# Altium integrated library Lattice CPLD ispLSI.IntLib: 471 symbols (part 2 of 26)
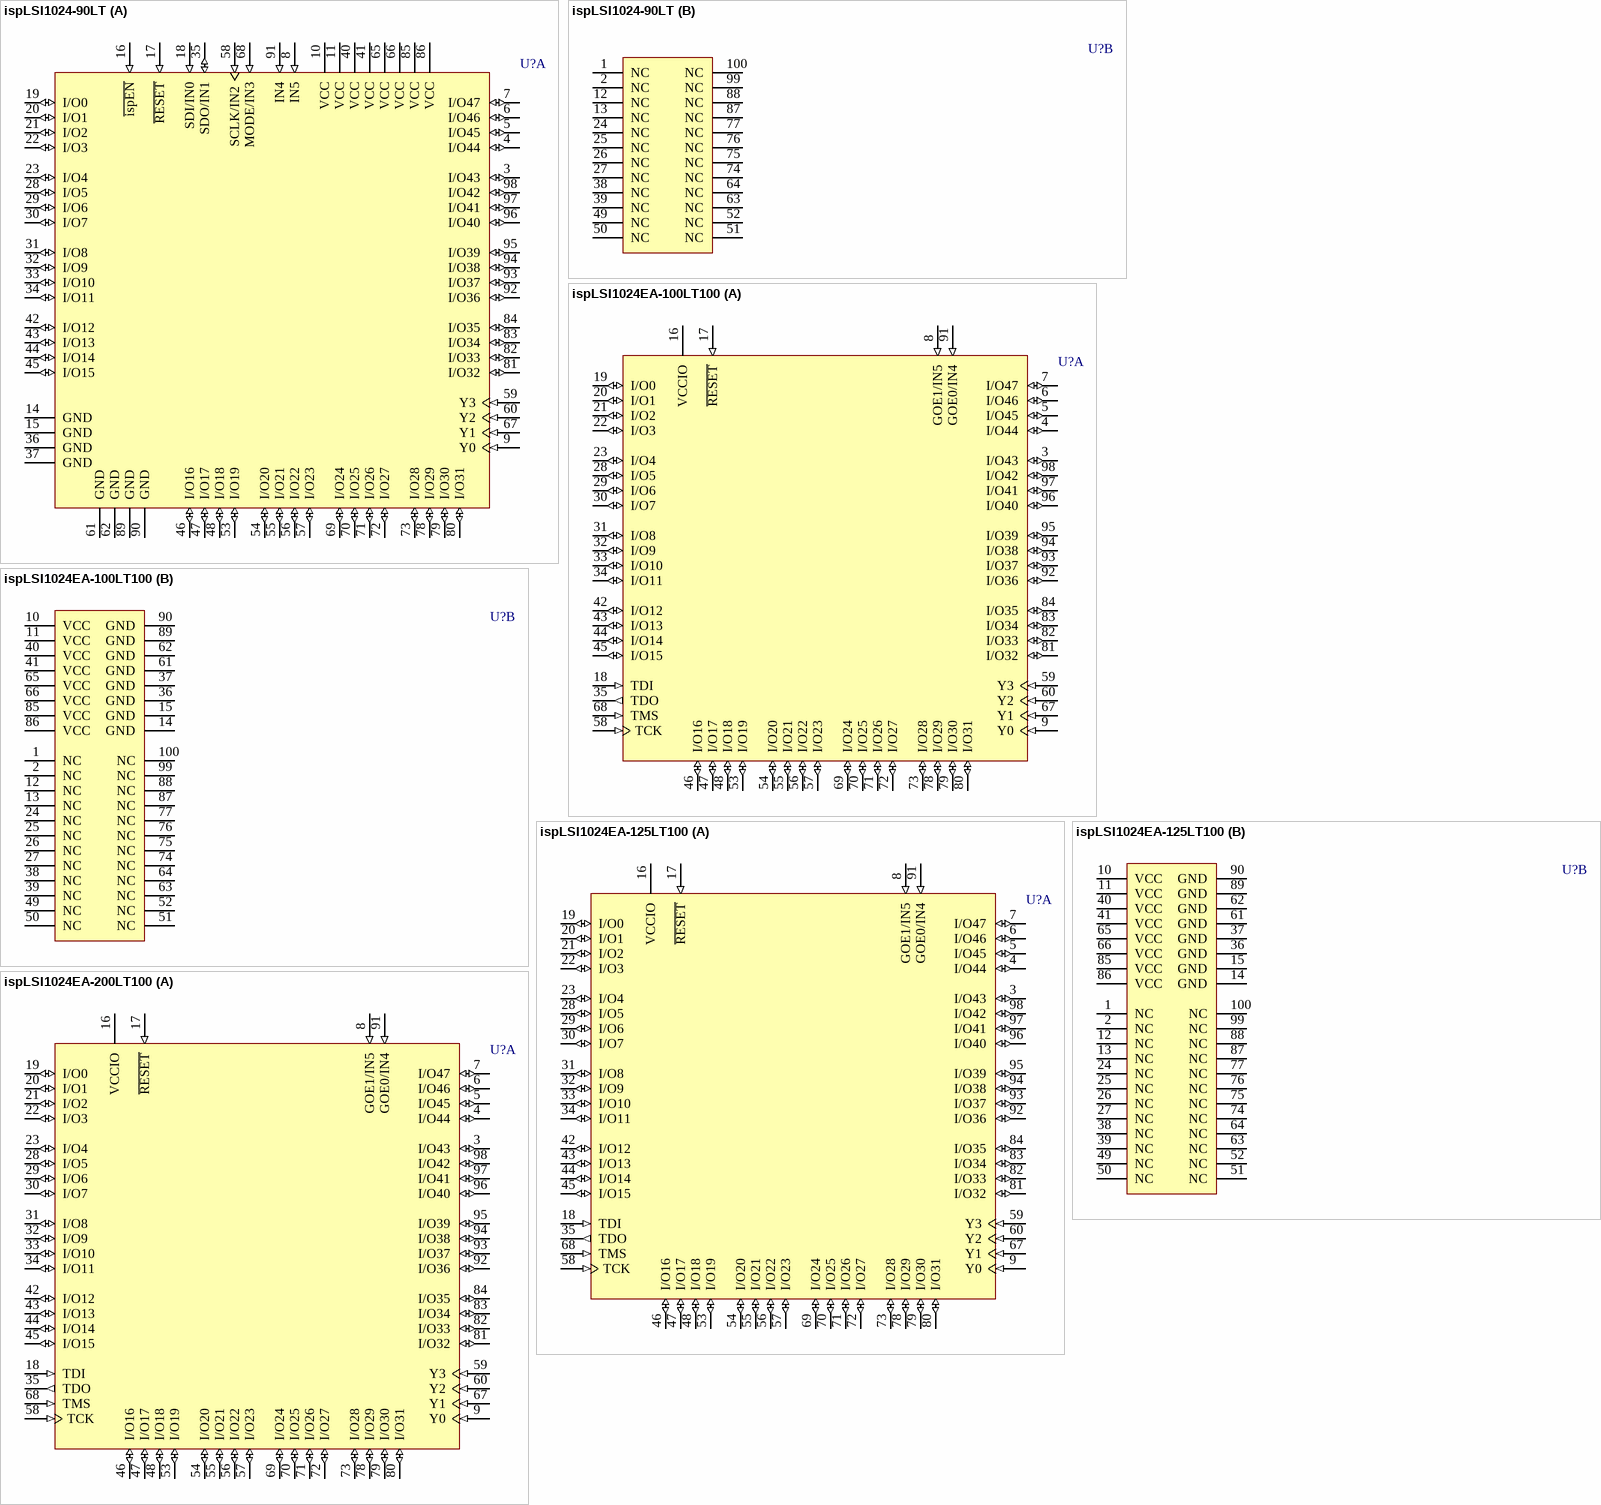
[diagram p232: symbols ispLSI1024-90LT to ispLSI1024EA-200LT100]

## ispLSI1024EA-100LT100
designator U?
In-System Programmable High-Density PLD; Note: Pins 8 and 91 have dual function capability which is software selectable.
footprint TQFP100_N (Thin QFP, 100-Leads, Body 14x14mm, Pitch 0.5mm, IPC Medium Density)
footprint TQFP100_L (Thin QFP, 100-Leads, Body 14x14mm, Pitch 0.5mm, IPC High Density)
footprint TQFP100_M (Thin QFP, 100-Leads, Body 14x14mm, Pitch 0.5mm, IPC Low Density)
3D model 1024EA-TQFP100 (100-Pin Thin Quad Flat Pack (TQFP100))
part A pins: 3 I/O43 (io), 4 I/O44 (io), 5 I/O45 (io), 6 I/O46 (io), 7 I/O47 (io), 8 GOE1/IN5 (in), 9 Y0 (in), 16 VCCIO (power), 17 ~{RESET} (in), 18 TDI (in), 19 I/O0 (io), 20 I/O1 (io), 21 I/O2 (io), 22 I/O3 (io), 23 I/O4 (io), 28 I/O5 (io), 29 I/O6 (io), 30 I/O7 (io), 31 I/O8 (io), 32 I/O9 (io), 33 I/O10 (io), 34 I/O11 (io), 35 TDO (out), 42 I/O12 (io), 43 I/O13 (io), 44 I/O14 (io), 45 I/O15 (io), 46 I/O16 (io), 47 I/O17 (io), 48 I/O18 (io), 53 I/O19 (io), 54 I/O20 (io), 55 I/O21 (io), 56 I/O22 (io), 57 I/O23 (io), 58 TCK (in), 59 Y3 (in), 60 Y2 (in), 67 Y1 (in), 68 TMS (in), 69 I/O24 (io), 70 I/O25 (io), 71 I/O26 (io), 72 I/O27 (io), 73 I/O28 (io), 78 I/O29 (io), 79 I/O30 (io), 80 I/O31 (io), 81 I/O32 (io), 82 I/O33 (io), 83 I/O34 (io), 84 I/O35 (io), 91 GOE0/IN4 (in), 92 I/O36 (io), 93 I/O37 (io), 94 I/O38 (io), 95 I/O39 (io), 96 I/O40 (io), 97 I/O41 (io), 98 I/O42 (io)
part B pins: 1 NC, 2 NC, 10 VCC (power), 11 VCC (power), 12 NC, 13 NC, 14 GND (power), 15 GND (power), 24 NC, 25 NC, 26 NC, 27 NC, 36 GND (power), 37 GND (power), 38 NC, 39 NC, 40 VCC (power), 41 VCC (power), 49 NC, 50 NC, 51 NC, 52 NC, 61 GND (power), 62 GND (power), 63 NC, 64 NC, 65 VCC (power), 66 VCC (power), 74 NC, 75 NC, 76 NC, 77 NC, 85 VCC (power), 86 VCC (power), 87 NC, 88 NC, 89 GND (power), 90 GND (power), 99 NC, 100 NC

## ispLSI1024EA-125LT100
designator U?
In-System Programmable High-Density PLD; Note: Pins 8 and 91 have dual function capability which is software selectable.
footprint TQFP100_N (Thin QFP, 100-Leads, Body 14x14mm, Pitch 0.5mm, IPC Medium Density)
footprint TQFP100_L (Thin QFP, 100-Leads, Body 14x14mm, Pitch 0.5mm, IPC High Density)
footprint TQFP100_M (Thin QFP, 100-Leads, Body 14x14mm, Pitch 0.5mm, IPC Low Density)
3D model 1024EA-TQFP100 (100-Pin Thin Quad Flat Pack (TQFP100))
part A pins: 3 I/O43 (io), 4 I/O44 (io), 5 I/O45 (io), 6 I/O46 (io), 7 I/O47 (io), 8 GOE1/IN5 (in), 9 Y0 (in), 16 VCCIO (power), 17 ~{RESET} (in), 18 TDI (in), 19 I/O0 (io), 20 I/O1 (io), 21 I/O2 (io), 22 I/O3 (io), 23 I/O4 (io), 28 I/O5 (io), 29 I/O6 (io), 30 I/O7 (io), 31 I/O8 (io), 32 I/O9 (io), 33 I/O10 (io), 34 I/O11 (io), 35 TDO (out), 42 I/O12 (io), 43 I/O13 (io), 44 I/O14 (io), 45 I/O15 (io), 46 I/O16 (io), 47 I/O17 (io), 48 I/O18 (io), 53 I/O19 (io), 54 I/O20 (io), 55 I/O21 (io), 56 I/O22 (io), 57 I/O23 (io), 58 TCK (in), 59 Y3 (in), 60 Y2 (in), 67 Y1 (in), 68 TMS (in), 69 I/O24 (io), 70 I/O25 (io), 71 I/O26 (io), 72 I/O27 (io), 73 I/O28 (io), 78 I/O29 (io), 79 I/O30 (io), 80 I/O31 (io), 81 I/O32 (io), 82 I/O33 (io), 83 I/O34 (io), 84 I/O35 (io), 91 GOE0/IN4 (in), 92 I/O36 (io), 93 I/O37 (io), 94 I/O38 (io), 95 I/O39 (io), 96 I/O40 (io), 97 I/O41 (io), 98 I/O42 (io)
part B pins: 1 NC, 2 NC, 10 VCC (power), 11 VCC (power), 12 NC, 13 NC, 14 GND (power), 15 GND (power), 24 NC, 25 NC, 26 NC, 27 NC, 36 GND (power), 37 GND (power), 38 NC, 39 NC, 40 VCC (power), 41 VCC (power), 49 NC, 50 NC, 51 NC, 52 NC, 61 GND (power), 62 GND (power), 63 NC, 64 NC, 65 VCC (power), 66 VCC (power), 74 NC, 75 NC, 76 NC, 77 NC, 85 VCC (power), 86 VCC (power), 87 NC, 88 NC, 89 GND (power), 90 GND (power), 99 NC, 100 NC

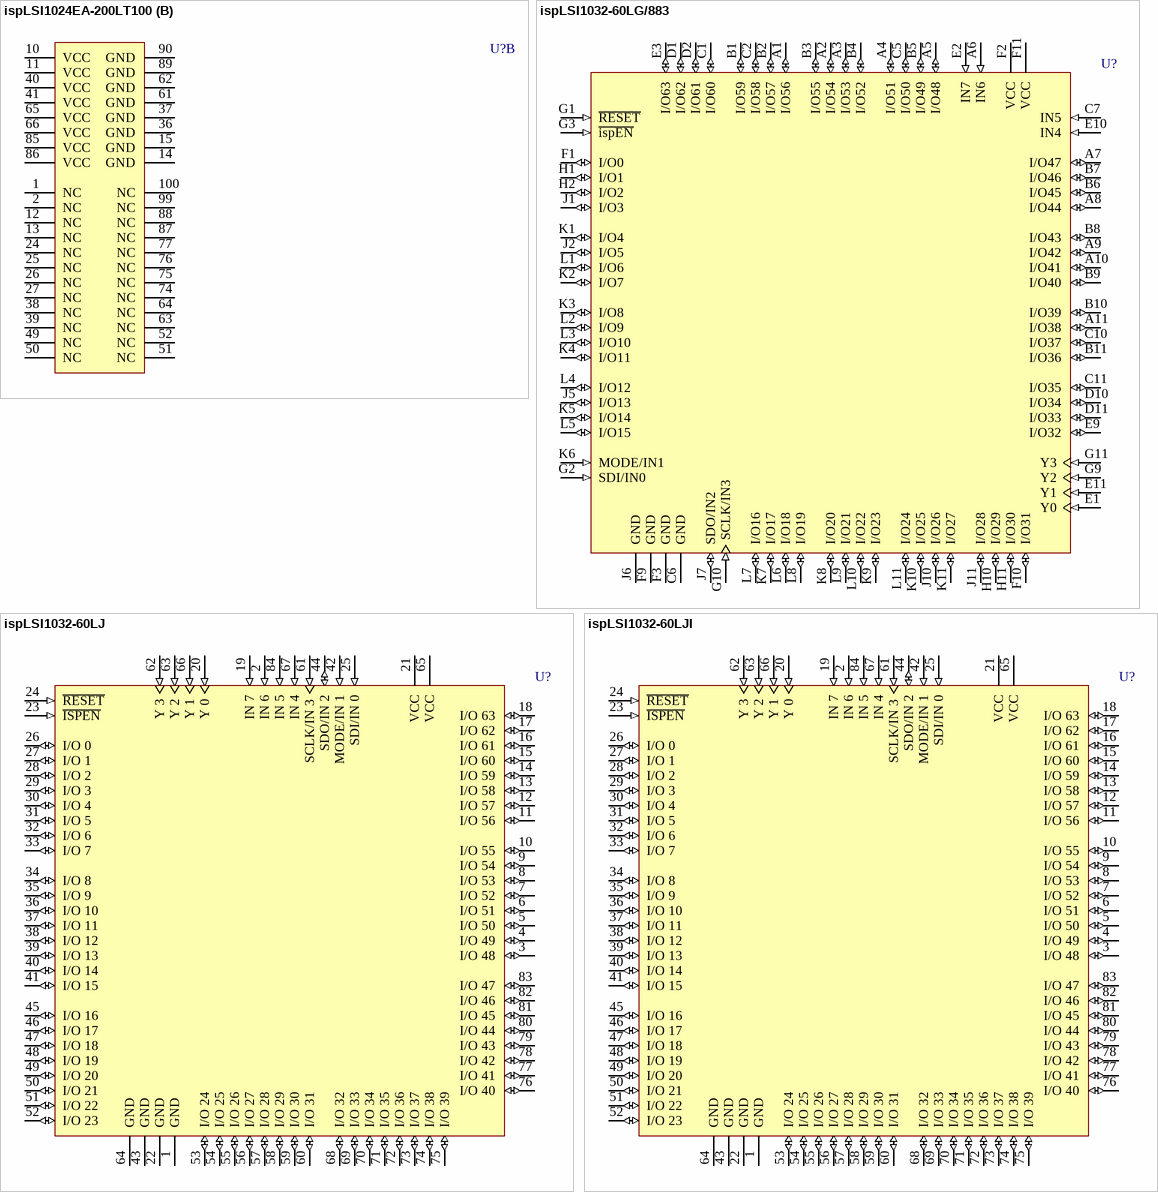
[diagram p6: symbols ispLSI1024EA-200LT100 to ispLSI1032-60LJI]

## ispLSI1024EA-200LT100
designator U?
In-System Programmable High-Density PLD; Note: Pins 8 and 91 have dual function capability which is software selectable.
footprint TQFP100_N (Thin QFP, 100-Leads, Body 14x14mm, Pitch 0.5mm, IPC Medium Density)
footprint TQFP100_L (Thin QFP, 100-Leads, Body 14x14mm, Pitch 0.5mm, IPC High Density)
footprint TQFP100_M (Thin QFP, 100-Leads, Body 14x14mm, Pitch 0.5mm, IPC Low Density)
3D model 1024EA-TQFP100 (100-Pin Thin Quad Flat Pack (TQFP100))
part A pins: 3 I/O43 (io), 4 I/O44 (io), 5 I/O45 (io), 6 I/O46 (io), 7 I/O47 (io), 8 GOE1/IN5 (in), 9 Y0 (in), 16 VCCIO (power), 17 ~{RESET} (in), 18 TDI (in), 19 I/O0 (io), 20 I/O1 (io), 21 I/O2 (io), 22 I/O3 (io), 23 I/O4 (io), 28 I/O5 (io), 29 I/O6 (io), 30 I/O7 (io), 31 I/O8 (io), 32 I/O9 (io), 33 I/O10 (io), 34 I/O11 (io), 35 TDO (out), 42 I/O12 (io), 43 I/O13 (io), 44 I/O14 (io), 45 I/O15 (io), 46 I/O16 (io), 47 I/O17 (io), 48 I/O18 (io), 53 I/O19 (io), 54 I/O20 (io), 55 I/O21 (io), 56 I/O22 (io), 57 I/O23 (io), 58 TCK (in), 59 Y3 (in), 60 Y2 (in), 67 Y1 (in), 68 TMS (in), 69 I/O24 (io), 70 I/O25 (io), 71 I/O26 (io), 72 I/O27 (io), 73 I/O28 (io), 78 I/O29 (io), 79 I/O30 (io), 80 I/O31 (io), 81 I/O32 (io), 82 I/O33 (io), 83 I/O34 (io), 84 I/O35 (io), 91 GOE0/IN4 (in), 92 I/O36 (io), 93 I/O37 (io), 94 I/O38 (io), 95 I/O39 (io), 96 I/O40 (io), 97 I/O41 (io), 98 I/O42 (io)
part B pins: 1 NC, 2 NC, 10 VCC (power), 11 VCC (power), 12 NC, 13 NC, 14 GND (power), 15 GND (power), 24 NC, 25 NC, 26 NC, 27 NC, 36 GND (power), 37 GND (power), 38 NC, 39 NC, 40 VCC (power), 41 VCC (power), 49 NC, 50 NC, 51 NC, 52 NC, 61 GND (power), 62 GND (power), 63 NC, 64 NC, 65 VCC (power), 66 VCC (power), 74 NC, 75 NC, 76 NC, 77 NC, 85 VCC (power), 86 VCC (power), 87 NC, 88 NC, 89 GND (power), 90 GND (power), 99 NC, 100 NC

## ispLSI1032-60LG/883
designator U?
In-System Programmable High-Density PLD; Note: Pins G2, K6, J7 and G10 have dual function capability.
footprint CPGA84 (PGA, 85-Leads, Body 29.5x29.5mm, Pitch 2.54mm)
3D model 1032-CPGA84 (85-Pin Pin Grid Array 2.54 mm Pitch)
pins: A1 I/O56 (io), A2 I/O54 (io), A3 I/O53 (io), A4 I/O51 (io), A5 I/O48 (io), A6 IN6 (in), A7 I/O47 (io), A8 I/O44 (io), A9 I/O42 (io), A10 I/O41 (io), A11 I/O38 (io), B1 I/O59 (io), B2 I/O57 (io), B3 I/O55 (io), B4 I/O52 (io), B5 I/O49 (io), B6 I/O45 (io), B7 I/O46 (io), B8 I/O43 (io), B9 I/O40 (io), B10 I/O39 (io), B11 I/O36 (io), C1 I/O60 (io), C2 I/O58 (io), C5 I/O50 (io), C6 GND (power), C7 IN5 (in), C10 I/O37 (io), C11 I/O35 (io), D1 I/O62 (io), D2 I/O61 (io), D10 I/O34 (io), D11 I/O33 (io), E1 Y0 (in), E2 IN7 (in), E3 I/O63 (io), E9 I/O32 (io), E10 IN4 (in), E11 Y1 (in), F1 I/O0 (io), F2 VCC (power), F3 GND (power), F9 GND (power), F10 I/O31 (io), F11 VCC (power), G1 ~{RESET} (in), G2 SDI/IN0 (in), G3 ~{ispEN} (in), G9 Y2 (in), G10 SCLK/IN3 (in), G11 Y3 (in), H1 I/O1 (io), H2 I/O2 (io), H10 I/O29 (io), H11 I/O30 (io), J1 I/O3 (io), J2 I/O5 (io), J5 I/O13 (io), J6 GND (power), J7 SDO/IN2 (io), J10 I/O26 (io), J11 I/O28 (io), K1 I/O4 (io), K2 I/O7 (io), K3 I/O8 (io), K4 I/O11 (io), K5 I/O14 (io), K6 MODE/IN1 (in), K7 I/O17 (io), K8 I/O20 (io), K9 I/O23 (io), K10 I/O25 (io), K11 I/O27 (io), L1 I/O6 (io), L2 I/O9 (io), L3 I/O10 (io), L4 I/O12 (io), L5 I/O15 (io), L6 I/O18 (io), L7 I/O16 (io), L8 I/O19 (io), L9 I/O21 (io), L10 I/O22 (io), L11 I/O24 (io)

## ispLSI1032-60LJ
designator U?
High-Density Programmable Logic
footprint PLCC84_N (Leaded Chip Carrier, 84-Leads, Body 29.3x29.3mm, Pitch 1.27mm, IPC Medium Density)
footprint PLCC84_L (Leaded Chip Carrier, 84-Leads, Body 29.3x29.3mm, Pitch 1.27mm, IPC High Density)
footprint PLCC84_M (Leaded Chip Carrier, 84-Leads, Body 29.3x29.3mm, Pitch 1.27mm, IPC Low Density)
3D model 1032-PLCC84 (84-Pin Leaded Chip Carrier 1.27 mm Pitch)
pins: 1 GND (power), 2 IN 6 (in), 3 I/O 48 (io), 4 I/O 49 (io), 5 I/O 50 (io), 6 I/O 51 (io), 7 I/O 52 (io), 8 I/O 53 (io), 9 I/O 54 (io), 10 I/O 55 (io), 11 I/O 56 (io), 12 I/O 57 (io), 13 I/O 58 (io), 14 I/O 59 (io), 15 I/O 60 (io), 16 I/O 61 (io), 17 I/O 62 (io), 18 I/O 63 (io), 19 IN 7 (in), 20 Y 0 (in), 21 VCC (power), 22 GND (power), 23 ~{ISPEN} (in), 24 ~{RESET} (in), 25 SDI/IN 0 (in), 26 I/O 0 (io), 27 I/O 1 (io), 28 I/O 2 (io), 29 I/O 3 (io), 30 I/O 4 (io), 31 I/O 5 (io), 32 I/O 6 (io), 33 I/O 7 (io), 34 I/O 8 (io), 35 I/O 9 (io), 36 I/O 10 (io), 37 I/O 11 (io), 38 I/O 12 (io), 39 I/O 13 (io), 40 I/O 14 (io), 41 I/O 15 (io), 42 MODE/IN 1 (in), 43 GND (power), 44 SDO/IN 2 (io), 45 I/O 16 (io), 46 I/O 17 (io), 47 I/O 18 (io), 48 I/O 19 (io), 49 I/O 20 (io), 50 I/O 21 (io), 51 I/O 22 (io), 52 I/O 23 (io), 53 I/O 24 (io), 54 I/O 25 (io), 55 I/O 26 (io), 56 I/O 27 (io), 57 I/O 28 (io), 58 I/O 29 (io), 59 I/O 30 (io), 60 I/O 31 (io), 61 SCLK/IN 3 (in), 62 Y 3 (in), 63 Y 2 (in), 64 GND (power), 65 VCC (power), 66 Y 1 (in), 67 IN 4 (in), 68 I/O 32 (io), 69 I/O 33 (io), 70 I/O 34 (io), 71 I/O 35 (io), 72 I/O 36 (io), 73 I/O 37 (io), 74 I/O 38 (io), 75 I/O 39 (io), 76 I/O 40 (io), 77 I/O 41 (io), 78 I/O 42 (io), 79 I/O 43 (io), 80 I/O 44 (io), 81 I/O 45 (io), 82 I/O 46 (io), 83 I/O 47 (io), 84 IN 5 (in)

## ispLSI1032-60LJI
designator U?
High-Density Programmable Logic
footprint PLCC84_N (Leaded Chip Carrier, 84-Leads, Body 29.3x29.3mm, Pitch 1.27mm, IPC Medium Density)
footprint PLCC84_L (Leaded Chip Carrier, 84-Leads, Body 29.3x29.3mm, Pitch 1.27mm, IPC High Density)
footprint PLCC84_M (Leaded Chip Carrier, 84-Leads, Body 29.3x29.3mm, Pitch 1.27mm, IPC Low Density)
3D model 1032-PLCC84 (84-Pin Leaded Chip Carrier 1.27 mm Pitch)
pins: 1 GND (power), 2 IN 6 (in), 3 I/O 48 (io), 4 I/O 49 (io), 5 I/O 50 (io), 6 I/O 51 (io), 7 I/O 52 (io), 8 I/O 53 (io), 9 I/O 54 (io), 10 I/O 55 (io), 11 I/O 56 (io), 12 I/O 57 (io), 13 I/O 58 (io), 14 I/O 59 (io), 15 I/O 60 (io), 16 I/O 61 (io), 17 I/O 62 (io), 18 I/O 63 (io), 19 IN 7 (in), 20 Y 0 (in), 21 VCC (power), 22 GND (power), 23 ~{ISPEN} (in), 24 ~{RESET} (in), 25 SDI/IN 0 (in), 26 I/O 0 (io), 27 I/O 1 (io), 28 I/O 2 (io), 29 I/O 3 (io), 30 I/O 4 (io), 31 I/O 5 (io), 32 I/O 6 (io), 33 I/O 7 (io), 34 I/O 8 (io), 35 I/O 9 (io), 36 I/O 10 (io), 37 I/O 11 (io), 38 I/O 12 (io), 39 I/O 13 (io), 40 I/O 14 (io), 41 I/O 15 (io), 42 MODE/IN 1 (in), 43 GND (power), 44 SDO/IN 2 (io), 45 I/O 16 (io), 46 I/O 17 (io), 47 I/O 18 (io), 48 I/O 19 (io), 49 I/O 20 (io), 50 I/O 21 (io), 51 I/O 22 (io), 52 I/O 23 (io), 53 I/O 24 (io), 54 I/O 25 (io), 55 I/O 26 (io), 56 I/O 27 (io), 57 I/O 28 (io), 58 I/O 29 (io), 59 I/O 30 (io), 60 I/O 31 (io), 61 SCLK/IN 3 (in), 62 Y 3 (in), 63 Y 2 (in), 64 GND (power), 65 VCC (power), 66 Y 1 (in), 67 IN 4 (in), 68 I/O 32 (io), 69 I/O 33 (io), 70 I/O 34 (io), 71 I/O 35 (io), 72 I/O 36 (io), 73 I/O 37 (io), 74 I/O 38 (io), 75 I/O 39 (io), 76 I/O 40 (io), 77 I/O 41 (io), 78 I/O 42 (io), 79 I/O 43 (io), 80 I/O 44 (io), 81 I/O 45 (io), 82 I/O 46 (io), 83 I/O 47 (io), 84 IN 5 (in)

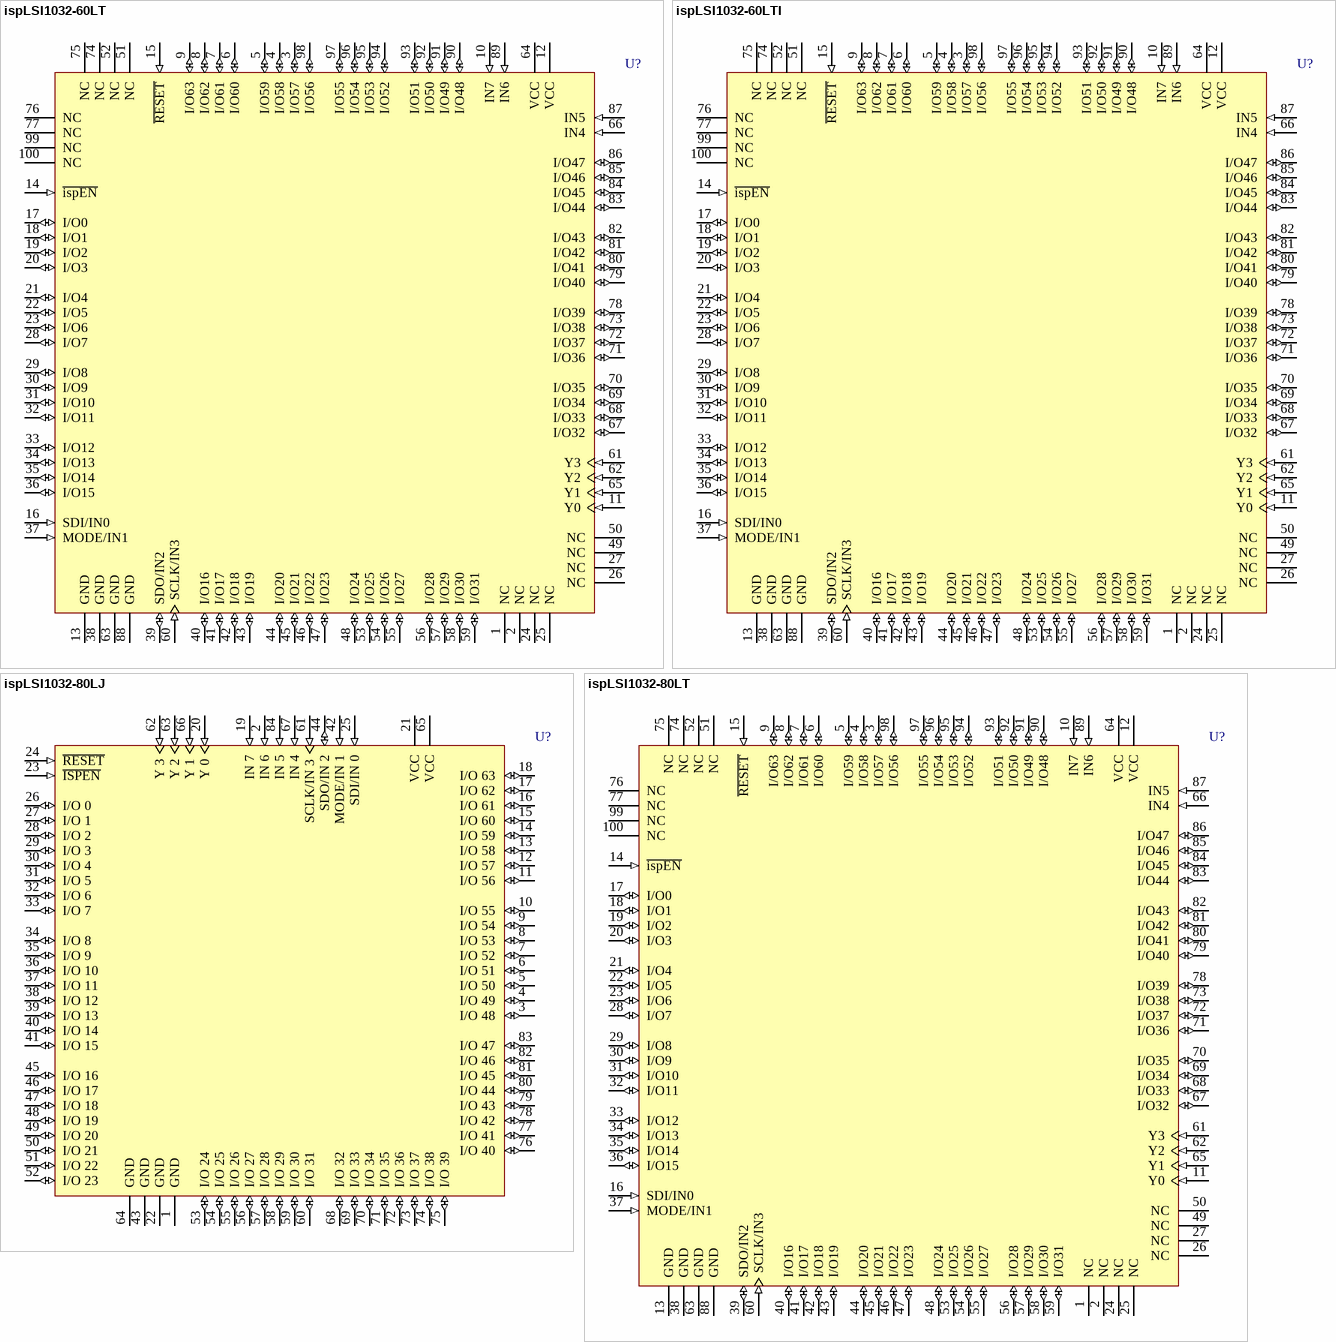
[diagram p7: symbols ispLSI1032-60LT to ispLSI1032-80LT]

## ispLSI1032-60LT
designator U?
High-Density Programmable Logic; Note: Pins 1, 2, 24-27, 49-52, 74-77, 99 and 100 are No internal Connection (NC) pins.
footprint TQFP100_N (Thin QFP, 100-Leads, Body 14x14mm, Pitch 0.5mm, IPC Medium Density)
footprint TQFP100_L (Thin QFP, 100-Leads, Body 14x14mm, Pitch 0.5mm, IPC High Density)
footprint TQFP100_M (Thin QFP, 100-Leads, Body 14x14mm, Pitch 0.5mm, IPC Low Density)
3D model 1032-TQFP100 (100-Pin Thin Quad Flat Pack (TQFP100))
pins: 1 NC, 2 NC, 3 I/O57 (io), 4 I/O58 (io), 5 I/O59 (io), 6 I/O60 (io), 7 I/O61 (io), 8 I/O62 (io), 9 I/O63 (io), 10 IN7 (in), 11 Y0 (in), 12 VCC (power), 13 GND (power), 14 ~{ispEN} (in), 15 ~{RESET} (in), 16 SDI/IN0 (in), 17 I/O0 (io), 18 I/O1 (io), 19 I/O2 (io), 20 I/O3 (io), 21 I/O4 (io), 22 I/O5 (io), 23 I/O6 (io), 24 NC, 25 NC, 26 NC, 27 NC, 28 I/O7 (io), 29 I/O8 (io), 30 I/O9 (io), 31 I/O10 (io), 32 I/O11 (io), 33 I/O12 (io), 34 I/O13 (io), 35 I/O14 (io), 36 I/O15 (io), 37 MODE/IN1 (in), 38 GND (power), 39 SDO/IN2 (io), 40 I/O16 (io), 41 I/O17 (io), 42 I/O18 (io), 43 I/O19 (io), 44 I/O20 (io), 45 I/O21 (io), 46 I/O22 (io), 47 I/O23 (io), 48 I/O24 (io), 49 NC, 50 NC, 51 NC, 52 NC, 53 I/O25 (io), 54 I/O26 (io), 55 I/O27 (io), 56 I/O28 (io), 57 I/O29 (io), 58 I/O30 (io), 59 I/O31 (io), 60 SCLK/IN3 (in), 61 Y3 (in), 62 Y2 (in), 63 GND (power), 64 VCC (power), 65 Y1 (in), 66 IN4 (in), 67 I/O32 (io), 68 I/O33 (io), 69 I/O34 (io), 70 I/O35 (io), 71 I/O36 (io), 72 I/O37 (io), 73 I/O38 (io), 74 NC, 75 NC, 76 NC, 77 NC, 78 I/O39 (io), 79 I/O40 (io), 80 I/O41 (io), 81 I/O42 (io), 82 I/O43 (io), 83 I/O44 (io), 84 I/O45 (io), 85 I/O46 (io), 86 I/O47 (io), 87 IN5 (in), 88 GND (power), 89 IN6 (in), 90 I/O48 (io), 91 I/O49 (io), 92 I/O50 (io), 93 I/O51 (io), 94 I/O52 (io), 95 I/O53 (io), 96 I/O54 (io), 97 I/O55 (io), 98 I/O56 (io), 99 NC, 100 NC

## ispLSI1032-60LTI
designator U?
In-System Programmable High-Density PLD; Note: Pins 16, 37, 39 and 60 have dual function capability.
footprint TQFP100_N (Thin QFP, 100-Leads, Body 14x14mm, Pitch 0.5mm, IPC Medium Density)
footprint TQFP100_L (Thin QFP, 100-Leads, Body 14x14mm, Pitch 0.5mm, IPC High Density)
footprint TQFP100_M (Thin QFP, 100-Leads, Body 14x14mm, Pitch 0.5mm, IPC Low Density)
3D model 1032-TQFP100 (100-Pin Thin Quad Flat Pack (TQFP100))
pins: 1 NC, 2 NC, 3 I/O57 (io), 4 I/O58 (io), 5 I/O59 (io), 6 I/O60 (io), 7 I/O61 (io), 8 I/O62 (io), 9 I/O63 (io), 10 IN7 (in), 11 Y0 (in), 12 VCC (power), 13 GND (power), 14 ~{ispEN} (in), 15 ~{RESET} (in), 16 SDI/IN0 (in), 17 I/O0 (io), 18 I/O1 (io), 19 I/O2 (io), 20 I/O3 (io), 21 I/O4 (io), 22 I/O5 (io), 23 I/O6 (io), 24 NC, 25 NC, 26 NC, 27 NC, 28 I/O7 (io), 29 I/O8 (io), 30 I/O9 (io), 31 I/O10 (io), 32 I/O11 (io), 33 I/O12 (io), 34 I/O13 (io), 35 I/O14 (io), 36 I/O15 (io), 37 MODE/IN1 (in), 38 GND (power), 39 SDO/IN2 (io), 40 I/O16 (io), 41 I/O17 (io), 42 I/O18 (io), 43 I/O19 (io), 44 I/O20 (io), 45 I/O21 (io), 46 I/O22 (io), 47 I/O23 (io), 48 I/O24 (io), 49 NC, 50 NC, 51 NC, 52 NC, 53 I/O25 (io), 54 I/O26 (io), 55 I/O27 (io), 56 I/O28 (io), 57 I/O29 (io), 58 I/O30 (io), 59 I/O31 (io), 60 SCLK/IN3 (in), 61 Y3 (in), 62 Y2 (in), 63 GND (power), 64 VCC (power), 65 Y1 (in), 66 IN4 (in), 67 I/O32 (io), 68 I/O33 (io), 69 I/O34 (io), 70 I/O35 (io), 71 I/O36 (io), 72 I/O37 (io), 73 I/O38 (io), 74 NC, 75 NC, 76 NC, 77 NC, 78 I/O39 (io), 79 I/O40 (io), 80 I/O41 (io), 81 I/O42 (io), 82 I/O43 (io), 83 I/O44 (io), 84 I/O45 (io), 85 I/O46 (io), 86 I/O47 (io), 87 IN5 (in), 88 GND (power), 89 IN6 (in), 90 I/O48 (io), 91 I/O49 (io), 92 I/O50 (io), 93 I/O51 (io), 94 I/O52 (io), 95 I/O53 (io), 96 I/O54 (io), 97 I/O55 (io), 98 I/O56 (io), 99 NC, 100 NC

## ispLSI1032-80LJ
designator U?
High-Density Programmable Logic
footprint PLCC84_N (Leaded Chip Carrier, 84-Leads, Body 29.3x29.3mm, Pitch 1.27mm, IPC Medium Density)
footprint PLCC84_L (Leaded Chip Carrier, 84-Leads, Body 29.3x29.3mm, Pitch 1.27mm, IPC High Density)
footprint PLCC84_M (Leaded Chip Carrier, 84-Leads, Body 29.3x29.3mm, Pitch 1.27mm, IPC Low Density)
3D model 1032-PLCC84 (84-Pin Leaded Chip Carrier 1.27 mm Pitch)
pins: 1 GND (power), 2 IN 6 (in), 3 I/O 48 (io), 4 I/O 49 (io), 5 I/O 50 (io), 6 I/O 51 (io), 7 I/O 52 (io), 8 I/O 53 (io), 9 I/O 54 (io), 10 I/O 55 (io), 11 I/O 56 (io), 12 I/O 57 (io), 13 I/O 58 (io), 14 I/O 59 (io), 15 I/O 60 (io), 16 I/O 61 (io), 17 I/O 62 (io), 18 I/O 63 (io), 19 IN 7 (in), 20 Y 0 (in), 21 VCC (power), 22 GND (power), 23 ~{ISPEN} (in), 24 ~{RESET} (in), 25 SDI/IN 0 (in), 26 I/O 0 (io), 27 I/O 1 (io), 28 I/O 2 (io), 29 I/O 3 (io), 30 I/O 4 (io), 31 I/O 5 (io), 32 I/O 6 (io), 33 I/O 7 (io), 34 I/O 8 (io), 35 I/O 9 (io), 36 I/O 10 (io), 37 I/O 11 (io), 38 I/O 12 (io), 39 I/O 13 (io), 40 I/O 14 (io), 41 I/O 15 (io), 42 MODE/IN 1 (in), 43 GND (power), 44 SDO/IN 2 (io), 45 I/O 16 (io), 46 I/O 17 (io), 47 I/O 18 (io), 48 I/O 19 (io), 49 I/O 20 (io), 50 I/O 21 (io), 51 I/O 22 (io), 52 I/O 23 (io), 53 I/O 24 (io), 54 I/O 25 (io), 55 I/O 26 (io), 56 I/O 27 (io), 57 I/O 28 (io), 58 I/O 29 (io), 59 I/O 30 (io), 60 I/O 31 (io), 61 SCLK/IN 3 (in), 62 Y 3 (in), 63 Y 2 (in), 64 GND (power), 65 VCC (power), 66 Y 1 (in), 67 IN 4 (in), 68 I/O 32 (io), 69 I/O 33 (io), 70 I/O 34 (io), 71 I/O 35 (io), 72 I/O 36 (io), 73 I/O 37 (io), 74 I/O 38 (io), 75 I/O 39 (io), 76 I/O 40 (io), 77 I/O 41 (io), 78 I/O 42 (io), 79 I/O 43 (io), 80 I/O 44 (io), 81 I/O 45 (io), 82 I/O 46 (io), 83 I/O 47 (io), 84 IN 5 (in)

## ispLSI1032-80LT
designator U?
High-Density Programmable Logic; Note: Pins 1, 2, 24-27, 49-52, 74-77, 99 and 100 are No internal Connection (NC) pins.
footprint TQFP100_N (Thin QFP, 100-Leads, Body 14x14mm, Pitch 0.5mm, IPC Medium Density)
footprint TQFP100_L (Thin QFP, 100-Leads, Body 14x14mm, Pitch 0.5mm, IPC High Density)
footprint TQFP100_M (Thin QFP, 100-Leads, Body 14x14mm, Pitch 0.5mm, IPC Low Density)
3D model 1032-TQFP100 (100-Pin Thin Quad Flat Pack (TQFP100))
pins: 1 NC, 2 NC, 3 I/O57 (io), 4 I/O58 (io), 5 I/O59 (io), 6 I/O60 (io), 7 I/O61 (io), 8 I/O62 (io), 9 I/O63 (io), 10 IN7 (in), 11 Y0 (in), 12 VCC (power), 13 GND (power), 14 ~{ispEN} (in), 15 ~{RESET} (in), 16 SDI/IN0 (in), 17 I/O0 (io), 18 I/O1 (io), 19 I/O2 (io), 20 I/O3 (io), 21 I/O4 (io), 22 I/O5 (io), 23 I/O6 (io), 24 NC, 25 NC, 26 NC, 27 NC, 28 I/O7 (io), 29 I/O8 (io), 30 I/O9 (io), 31 I/O10 (io), 32 I/O11 (io), 33 I/O12 (io), 34 I/O13 (io), 35 I/O14 (io), 36 I/O15 (io), 37 MODE/IN1 (in), 38 GND (power), 39 SDO/IN2 (io), 40 I/O16 (io), 41 I/O17 (io), 42 I/O18 (io), 43 I/O19 (io), 44 I/O20 (io), 45 I/O21 (io), 46 I/O22 (io), 47 I/O23 (io), 48 I/O24 (io), 49 NC, 50 NC, 51 NC, 52 NC, 53 I/O25 (io), 54 I/O26 (io), 55 I/O27 (io), 56 I/O28 (io), 57 I/O29 (io), 58 I/O30 (io), 59 I/O31 (io), 60 SCLK/IN3 (in), 61 Y3 (in), 62 Y2 (in), 63 GND (power), 64 VCC (power), 65 Y1 (in), 66 IN4 (in), 67 I/O32 (io), 68 I/O33 (io), 69 I/O34 (io), 70 I/O35 (io), 71 I/O36 (io), 72 I/O37 (io), 73 I/O38 (io), 74 NC, 75 NC, 76 NC, 77 NC, 78 I/O39 (io), 79 I/O40 (io), 80 I/O41 (io), 81 I/O42 (io), 82 I/O43 (io), 83 I/O44 (io), 84 I/O45 (io), 85 I/O46 (io), 86 I/O47 (io), 87 IN5 (in), 88 GND (power), 89 IN6 (in), 90 I/O48 (io), 91 I/O49 (io), 92 I/O50 (io), 93 I/O51 (io), 94 I/O52 (io), 95 I/O53 (io), 96 I/O54 (io), 97 I/O55 (io), 98 I/O56 (io), 99 NC, 100 NC

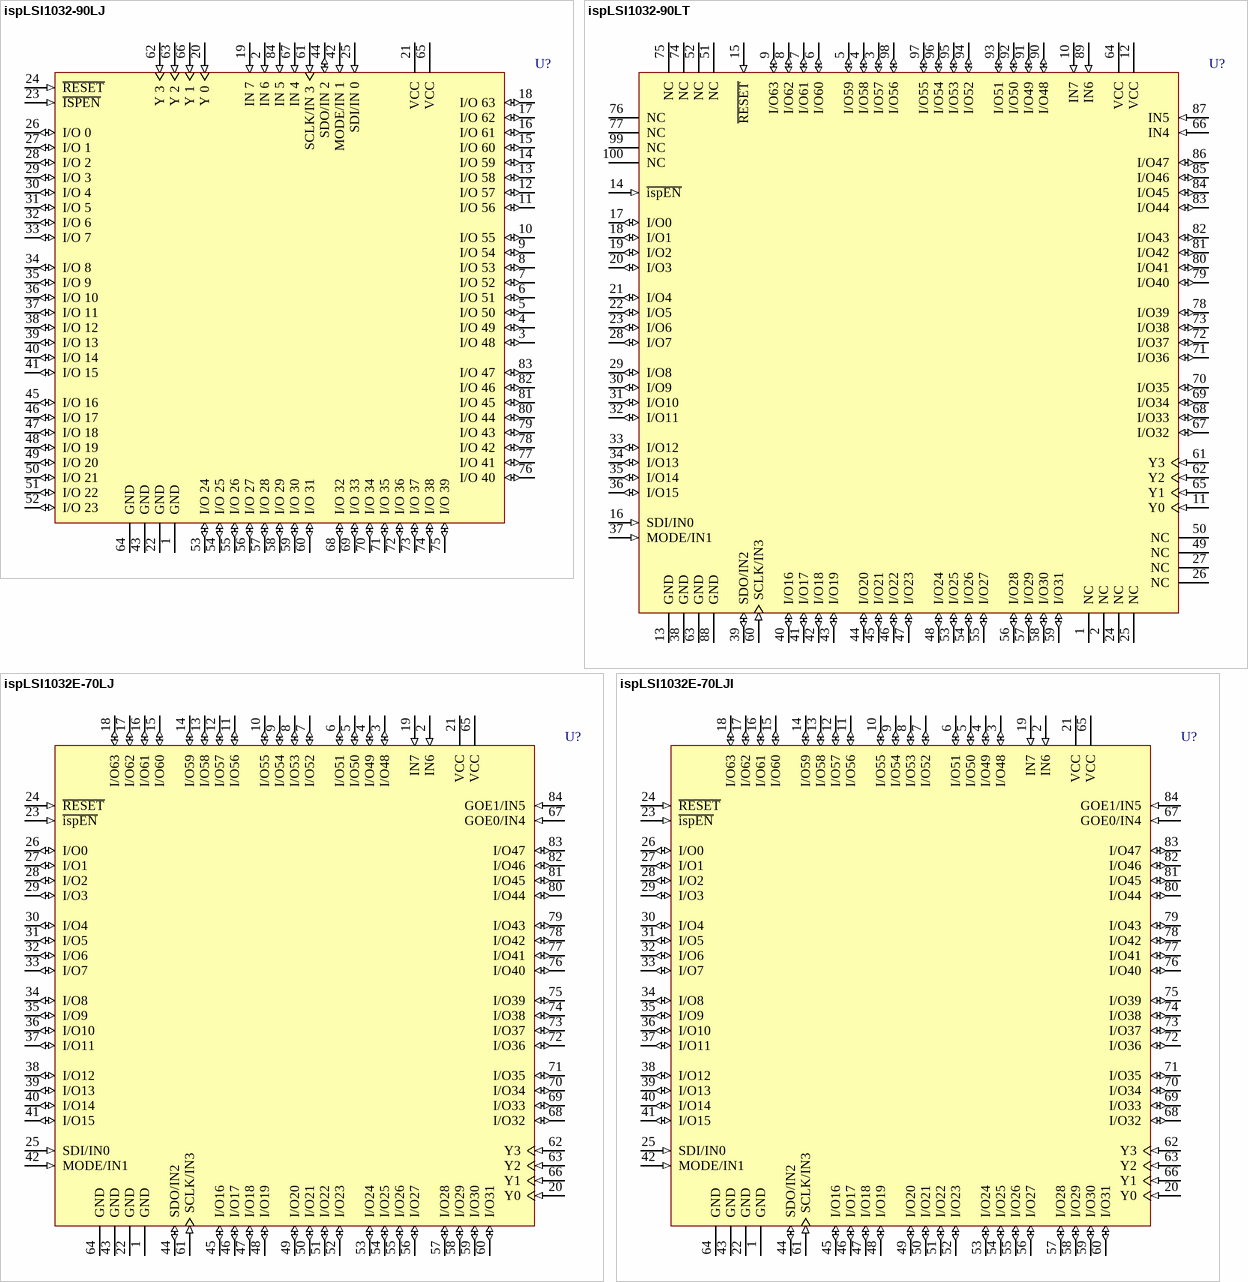
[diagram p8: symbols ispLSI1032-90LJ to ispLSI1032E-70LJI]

## ispLSI1032-90LJ
designator U?
High-Density Programmable Logic
footprint PLCC84_N (Leaded Chip Carrier, 84-Leads, Body 29.3x29.3mm, Pitch 1.27mm, IPC Medium Density)
footprint PLCC84_L (Leaded Chip Carrier, 84-Leads, Body 29.3x29.3mm, Pitch 1.27mm, IPC High Density)
footprint PLCC84_M (Leaded Chip Carrier, 84-Leads, Body 29.3x29.3mm, Pitch 1.27mm, IPC Low Density)
3D model 1032-PLCC84 (84-Pin Leaded Chip Carrier 1.27 mm Pitch)
pins: 1 GND (power), 2 IN 6 (in), 3 I/O 48 (io), 4 I/O 49 (io), 5 I/O 50 (io), 6 I/O 51 (io), 7 I/O 52 (io), 8 I/O 53 (io), 9 I/O 54 (io), 10 I/O 55 (io), 11 I/O 56 (io), 12 I/O 57 (io), 13 I/O 58 (io), 14 I/O 59 (io), 15 I/O 60 (io), 16 I/O 61 (io), 17 I/O 62 (io), 18 I/O 63 (io), 19 IN 7 (in), 20 Y 0 (in), 21 VCC (power), 22 GND (power), 23 ~{ISPEN} (in), 24 ~{RESET} (in), 25 SDI/IN 0 (in), 26 I/O 0 (io), 27 I/O 1 (io), 28 I/O 2 (io), 29 I/O 3 (io), 30 I/O 4 (io), 31 I/O 5 (io), 32 I/O 6 (io), 33 I/O 7 (io), 34 I/O 8 (io), 35 I/O 9 (io), 36 I/O 10 (io), 37 I/O 11 (io), 38 I/O 12 (io), 39 I/O 13 (io), 40 I/O 14 (io), 41 I/O 15 (io), 42 MODE/IN 1 (in), 43 GND (power), 44 SDO/IN 2 (io), 45 I/O 16 (io), 46 I/O 17 (io), 47 I/O 18 (io), 48 I/O 19 (io), 49 I/O 20 (io), 50 I/O 21 (io), 51 I/O 22 (io), 52 I/O 23 (io), 53 I/O 24 (io), 54 I/O 25 (io), 55 I/O 26 (io), 56 I/O 27 (io), 57 I/O 28 (io), 58 I/O 29 (io), 59 I/O 30 (io), 60 I/O 31 (io), 61 SCLK/IN 3 (in), 62 Y 3 (in), 63 Y 2 (in), 64 GND (power), 65 VCC (power), 66 Y 1 (in), 67 IN 4 (in), 68 I/O 32 (io), 69 I/O 33 (io), 70 I/O 34 (io), 71 I/O 35 (io), 72 I/O 36 (io), 73 I/O 37 (io), 74 I/O 38 (io), 75 I/O 39 (io), 76 I/O 40 (io), 77 I/O 41 (io), 78 I/O 42 (io), 79 I/O 43 (io), 80 I/O 44 (io), 81 I/O 45 (io), 82 I/O 46 (io), 83 I/O 47 (io), 84 IN 5 (in)

## ispLSI1032-90LT
designator U?
High-Density Programmable Logic; Note: Pins 1, 2, 24-27, 49-52, 74-77, 99 and 100 are No internal Connection (NC) pins.
footprint TQFP100_N (Thin QFP, 100-Leads, Body 14x14mm, Pitch 0.5mm, IPC Medium Density)
footprint TQFP100_L (Thin QFP, 100-Leads, Body 14x14mm, Pitch 0.5mm, IPC High Density)
footprint TQFP100_M (Thin QFP, 100-Leads, Body 14x14mm, Pitch 0.5mm, IPC Low Density)
3D model 1032-TQFP100 (100-Pin Thin Quad Flat Pack (TQFP100))
pins: 1 NC, 2 NC, 3 I/O57 (io), 4 I/O58 (io), 5 I/O59 (io), 6 I/O60 (io), 7 I/O61 (io), 8 I/O62 (io), 9 I/O63 (io), 10 IN7 (in), 11 Y0 (in), 12 VCC (power), 13 GND (power), 14 ~{ispEN} (in), 15 ~{RESET} (in), 16 SDI/IN0 (in), 17 I/O0 (io), 18 I/O1 (io), 19 I/O2 (io), 20 I/O3 (io), 21 I/O4 (io), 22 I/O5 (io), 23 I/O6 (io), 24 NC, 25 NC, 26 NC, 27 NC, 28 I/O7 (io), 29 I/O8 (io), 30 I/O9 (io), 31 I/O10 (io), 32 I/O11 (io), 33 I/O12 (io), 34 I/O13 (io), 35 I/O14 (io), 36 I/O15 (io), 37 MODE/IN1 (in), 38 GND (power), 39 SDO/IN2 (io), 40 I/O16 (io), 41 I/O17 (io), 42 I/O18 (io), 43 I/O19 (io), 44 I/O20 (io), 45 I/O21 (io), 46 I/O22 (io), 47 I/O23 (io), 48 I/O24 (io), 49 NC, 50 NC, 51 NC, 52 NC, 53 I/O25 (io), 54 I/O26 (io), 55 I/O27 (io), 56 I/O28 (io), 57 I/O29 (io), 58 I/O30 (io), 59 I/O31 (io), 60 SCLK/IN3 (in), 61 Y3 (in), 62 Y2 (in), 63 GND (power), 64 VCC (power), 65 Y1 (in), 66 IN4 (in), 67 I/O32 (io), 68 I/O33 (io), 69 I/O34 (io), 70 I/O35 (io), 71 I/O36 (io), 72 I/O37 (io), 73 I/O38 (io), 74 NC, 75 NC, 76 NC, 77 NC, 78 I/O39 (io), 79 I/O40 (io), 80 I/O41 (io), 81 I/O42 (io), 82 I/O43 (io), 83 I/O44 (io), 84 I/O45 (io), 85 I/O46 (io), 86 I/O47 (io), 87 IN5 (in), 88 GND (power), 89 IN6 (in), 90 I/O48 (io), 91 I/O49 (io), 92 I/O50 (io), 93 I/O51 (io), 94 I/O52 (io), 95 I/O53 (io), 96 I/O54 (io), 97 I/O55 (io), 98 I/O56 (io), 99 NC, 100 NC

## ispLSI1032E-70LJ
designator U?
In-System Programmable High-Density PLD; Note: Pins 25, 42, 44, 61, 67 & 84 have dual function capability; Pins 67 & 84 are software selectable.
footprint PLCC84_N (Leaded Chip Carrier, 84-Leads, Body 29.3x29.3mm, Pitch 1.27mm, IPC Medium Density)
footprint PLCC84_L (Leaded Chip Carrier, 84-Leads, Body 29.3x29.3mm, Pitch 1.27mm, IPC High Density)
footprint PLCC84_M (Leaded Chip Carrier, 84-Leads, Body 29.3x29.3mm, Pitch 1.27mm, IPC Low Density)
3D model 1032E-PLCC84 (84-Pin Leaded Chip Carrier 1.27 mm Pitch)
pins: 1 GND (power), 2 IN6 (in), 3 I/O48 (io), 4 I/O49 (io), 5 I/O50 (io), 6 I/O51 (io), 7 I/O52 (io), 8 I/O53 (io), 9 I/O54 (io), 10 I/O55 (io), 11 I/O56 (io), 12 I/O57 (io), 13 I/O58 (io), 14 I/O59 (io), 15 I/O60 (io), 16 I/O61 (io), 17 I/O62 (io), 18 I/O63 (io), 19 IN7 (in), 20 Y0 (in), 21 VCC (power), 22 GND (power), 23 ~{isp}~{EN} (in), 24 ~{RESET} (in), 25 SDI/IN0 (in), 26 I/O0 (io), 27 I/O1 (io), 28 I/O2 (io), 29 I/O3 (io), 30 I/O4 (io), 31 I/O5 (io), 32 I/O6 (io), 33 I/O7 (io), 34 I/O8 (io), 35 I/O9 (io), 36 I/O10 (io), 37 I/O11 (io), 38 I/O12 (io), 39 I/O13 (io), 40 I/O14 (io), 41 I/O15 (io), 42 MODE/IN1 (in), 43 GND (power), 44 SDO/IN2 (io), 45 I/O16 (io), 46 I/O17 (io), 47 I/O18 (io), 48 I/O19 (io), 49 I/O20 (io), 50 I/O21 (io), 51 I/O22 (io), 52 I/O23 (io), 53 I/O24 (io), 54 I/O25 (io), 55 I/O26 (io), 56 I/O27 (io), 57 I/O28 (io), 58 I/O29 (io), 59 I/O30 (io), 60 I/O31 (io), 61 SCLK/IN3 (in), 62 Y3 (in), 63 Y2 (in), 64 GND (power), 65 VCC (power), 66 Y1 (in), 67 GOE0/IN4 (in), 68 I/O32 (io), 69 I/O33 (io), 70 I/O34 (io), 71 I/O35 (io), 72 I/O36 (io), 73 I/O37 (io), 74 I/O38 (io), 75 I/O39 (io), 76 I/O40 (io), 77 I/O41 (io), 78 I/O42 (io), 79 I/O43 (io), 80 I/O44 (io), 81 I/O45 (io), 82 I/O46 (io), 83 I/O47 (io), 84 GOE1/IN5 (in)

## ispLSI1032E-70LJI
designator U?
In-System Programmable High-Density PLD; Note: Pins 25, 42, 44, 61, 67 & 84 have dual function capability; Pins 67 & 84 are software selectable.
footprint PLCC84_N (Leaded Chip Carrier, 84-Leads, Body 29.3x29.3mm, Pitch 1.27mm, IPC Medium Density)
footprint PLCC84_L (Leaded Chip Carrier, 84-Leads, Body 29.3x29.3mm, Pitch 1.27mm, IPC High Density)
footprint PLCC84_M (Leaded Chip Carrier, 84-Leads, Body 29.3x29.3mm, Pitch 1.27mm, IPC Low Density)
3D model 1032E-PLCC84 (84-Pin Leaded Chip Carrier 1.27 mm Pitch)
pins: 1 GND (power), 2 IN6 (in), 3 I/O48 (io), 4 I/O49 (io), 5 I/O50 (io), 6 I/O51 (io), 7 I/O52 (io), 8 I/O53 (io), 9 I/O54 (io), 10 I/O55 (io), 11 I/O56 (io), 12 I/O57 (io), 13 I/O58 (io), 14 I/O59 (io), 15 I/O60 (io), 16 I/O61 (io), 17 I/O62 (io), 18 I/O63 (io), 19 IN7 (in), 20 Y0 (in), 21 VCC (power), 22 GND (power), 23 ~{isp}~{EN} (in), 24 ~{RESET} (in), 25 SDI/IN0 (in), 26 I/O0 (io), 27 I/O1 (io), 28 I/O2 (io), 29 I/O3 (io), 30 I/O4 (io), 31 I/O5 (io), 32 I/O6 (io), 33 I/O7 (io), 34 I/O8 (io), 35 I/O9 (io), 36 I/O10 (io), 37 I/O11 (io), 38 I/O12 (io), 39 I/O13 (io), 40 I/O14 (io), 41 I/O15 (io), 42 MODE/IN1 (in), 43 GND (power), 44 SDO/IN2 (io), 45 I/O16 (io), 46 I/O17 (io), 47 I/O18 (io), 48 I/O19 (io), 49 I/O20 (io), 50 I/O21 (io), 51 I/O22 (io), 52 I/O23 (io), 53 I/O24 (io), 54 I/O25 (io), 55 I/O26 (io), 56 I/O27 (io), 57 I/O28 (io), 58 I/O29 (io), 59 I/O30 (io), 60 I/O31 (io), 61 SCLK/IN3 (in), 62 Y3 (in), 63 Y2 (in), 64 GND (power), 65 VCC (power), 66 Y1 (in), 67 GOE0/IN4 (in), 68 I/O32 (io), 69 I/O33 (io), 70 I/O34 (io), 71 I/O35 (io), 72 I/O36 (io), 73 I/O37 (io), 74 I/O38 (io), 75 I/O39 (io), 76 I/O40 (io), 77 I/O41 (io), 78 I/O42 (io), 79 I/O43 (io), 80 I/O44 (io), 81 I/O45 (io), 82 I/O46 (io), 83 I/O47 (io), 84 GOE1/IN5 (in)

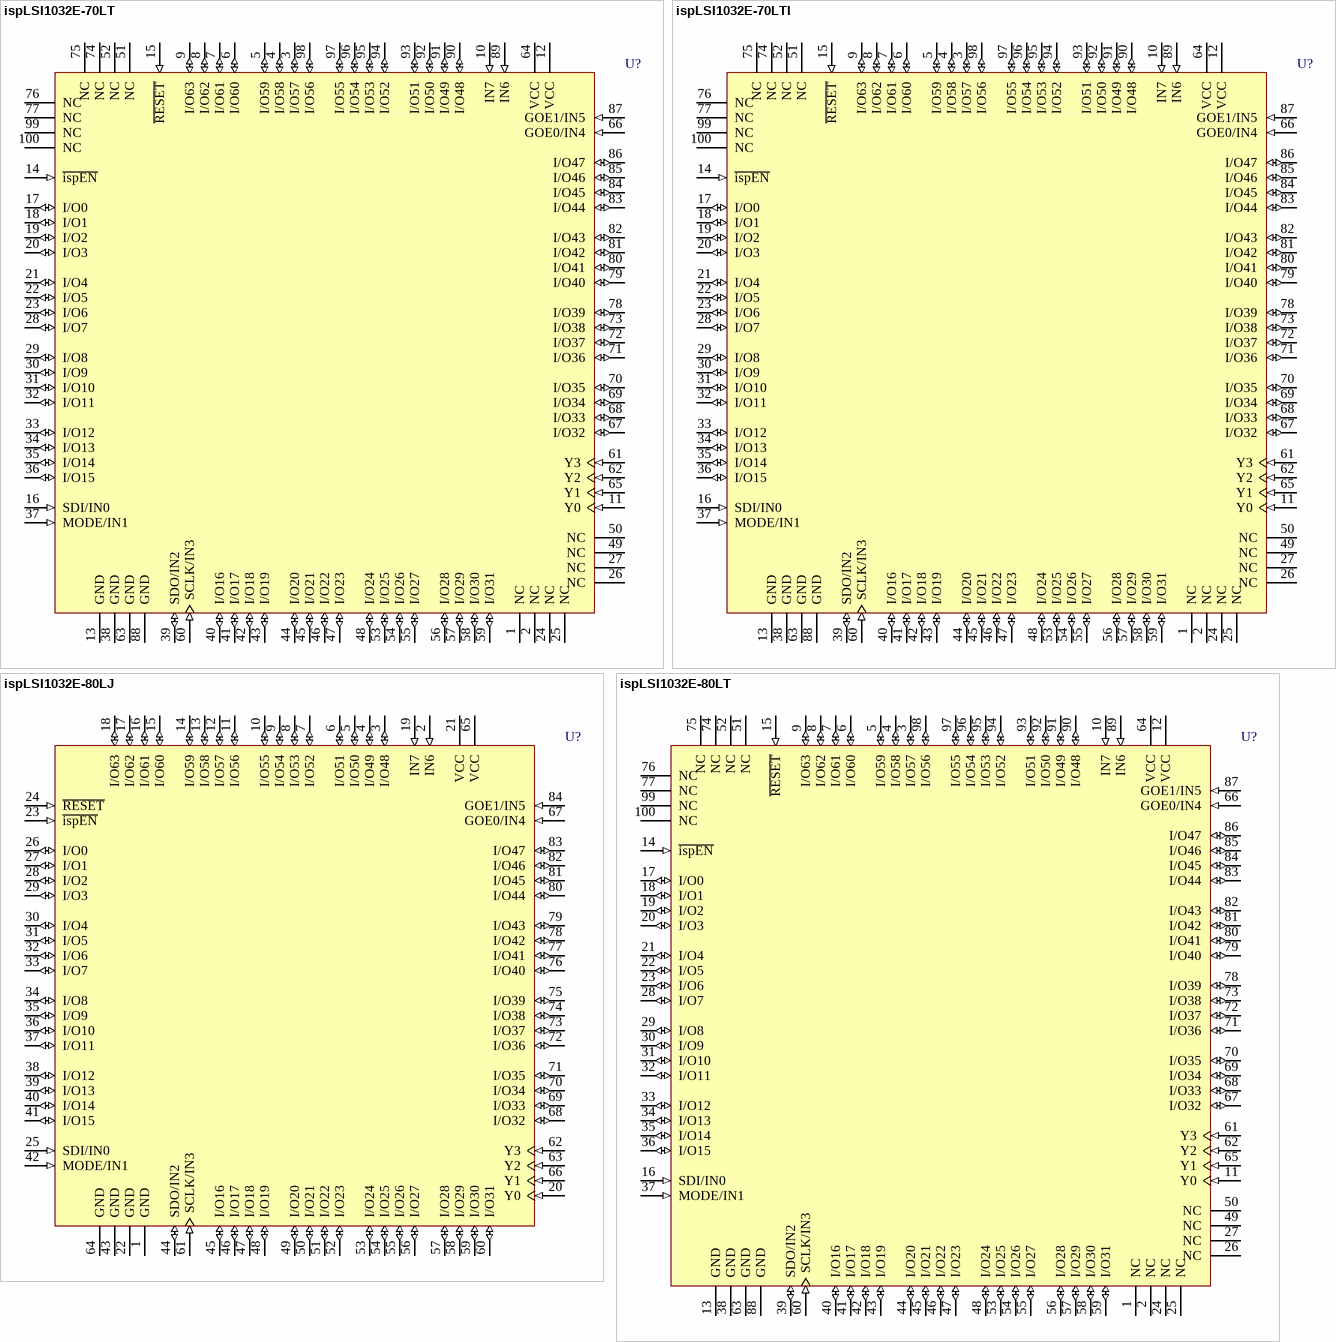
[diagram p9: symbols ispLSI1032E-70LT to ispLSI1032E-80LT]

## ispLSI1032E-70LT
designator U?
In-System Programmable High-Density PLD; Note: Pins 16, 37, 39, 60, 66 & 87 have dual function capability; Pins 66 & 87 are software selectable.
footprint TQFP100_N (Thin QFP, 100-Leads, Body 14x14mm, Pitch 0.5mm, IPC Medium Density)
footprint TQFP100_L (Thin QFP, 100-Leads, Body 14x14mm, Pitch 0.5mm, IPC High Density)
footprint TQFP100_M (Thin QFP, 100-Leads, Body 14x14mm, Pitch 0.5mm, IPC Low Density)
3D model 1032E-TQFP100 (100-Pin Thin Quad Flat Pack (TQFP100))
pins: 1 NC, 2 NC, 3 I/O57 (io), 4 I/O58 (io), 5 I/O59 (io), 6 I/O60 (io), 7 I/O61 (io), 8 I/O62 (io), 9 I/O63 (io), 10 IN7 (in), 11 Y0 (in), 12 VCC (power), 13 GND (power), 14 ~{ispEN} (in), 15 ~{RESET} (in), 16 SDI/IN0 (in), 17 I/O0 (io), 18 I/O1 (io), 19 I/O2 (io), 20 I/O3 (io), 21 I/O4 (io), 22 I/O5 (io), 23 I/O6 (io), 24 NC, 25 NC, 26 NC, 27 NC, 28 I/O7 (io), 29 I/O8 (io), 30 I/O9 (io), 31 I/O10 (io), 32 I/O11 (io), 33 I/O12 (io), 34 I/O13 (io), 35 I/O14 (io), 36 I/O15 (io), 37 MODE/IN1 (in), 38 GND (power), 39 SDO/IN2 (io), 40 I/O16 (io), 41 I/O17 (io), 42 I/O18 (io), 43 I/O19 (io), 44 I/O20 (io), 45 I/O21 (io), 46 I/O22 (io), 47 I/O23 (io), 48 I/O24 (io), 49 NC, 50 NC, 51 NC, 52 NC, 53 I/O25 (io), 54 I/O26 (io), 55 I/O27 (io), 56 I/O28 (io), 57 I/O29 (io), 58 I/O30 (io), 59 I/O31 (io), 60 SCLK/IN3 (in), 61 Y3 (in), 62 Y2 (in), 63 GND (power), 64 VCC (power), 65 Y1 (in), 66 GOE0/IN4 (in), 67 I/O32 (io), 68 I/O33 (io), 69 I/O34 (io), 70 I/O35 (io), 71 I/O36 (io), 72 I/O37 (io), 73 I/O38 (io), 74 NC, 75 NC, 76 NC, 77 NC, 78 I/O39 (io), 79 I/O40 (io), 80 I/O41 (io), 81 I/O42 (io), 82 I/O43 (io), 83 I/O44 (io), 84 I/O45 (io), 85 I/O46 (io), 86 I/O47 (io), 87 GOE1/IN5 (in), 88 GND (power), 89 IN6 (in), 90 I/O48 (io), 91 I/O49 (io), 92 I/O50 (io), 93 I/O51 (io), 94 I/O52 (io), 95 I/O53 (io), 96 I/O54 (io), 97 I/O55 (io), 98 I/O56 (io), 99 NC, 100 NC

## ispLSI1032E-70LTI
designator U?
In-System Programmable High-Density PLD; Note: Pins 16, 37, 39, 60, 66 & 87 have dual function capability; Pins 66 & 87 are software selectable.
footprint TQFP100_N (Thin QFP, 100-Leads, Body 14x14mm, Pitch 0.5mm, IPC Medium Density)
footprint TQFP100_L (Thin QFP, 100-Leads, Body 14x14mm, Pitch 0.5mm, IPC High Density)
footprint TQFP100_M (Thin QFP, 100-Leads, Body 14x14mm, Pitch 0.5mm, IPC Low Density)
3D model 1032E-TQFP100 (100-Pin Thin Quad Flat Pack (TQFP100))
pins: 1 NC, 2 NC, 3 I/O57 (io), 4 I/O58 (io), 5 I/O59 (io), 6 I/O60 (io), 7 I/O61 (io), 8 I/O62 (io), 9 I/O63 (io), 10 IN7 (in), 11 Y0 (in), 12 VCC (power), 13 GND (power), 14 ~{ispEN} (in), 15 ~{RESET} (in), 16 SDI/IN0 (in), 17 I/O0 (io), 18 I/O1 (io), 19 I/O2 (io), 20 I/O3 (io), 21 I/O4 (io), 22 I/O5 (io), 23 I/O6 (io), 24 NC, 25 NC, 26 NC, 27 NC, 28 I/O7 (io), 29 I/O8 (io), 30 I/O9 (io), 31 I/O10 (io), 32 I/O11 (io), 33 I/O12 (io), 34 I/O13 (io), 35 I/O14 (io), 36 I/O15 (io), 37 MODE/IN1 (in), 38 GND (power), 39 SDO/IN2 (io), 40 I/O16 (io), 41 I/O17 (io), 42 I/O18 (io), 43 I/O19 (io), 44 I/O20 (io), 45 I/O21 (io), 46 I/O22 (io), 47 I/O23 (io), 48 I/O24 (io), 49 NC, 50 NC, 51 NC, 52 NC, 53 I/O25 (io), 54 I/O26 (io), 55 I/O27 (io), 56 I/O28 (io), 57 I/O29 (io), 58 I/O30 (io), 59 I/O31 (io), 60 SCLK/IN3 (in), 61 Y3 (in), 62 Y2 (in), 63 GND (power), 64 VCC (power), 65 Y1 (in), 66 GOE0/IN4 (in), 67 I/O32 (io), 68 I/O33 (io), 69 I/O34 (io), 70 I/O35 (io), 71 I/O36 (io), 72 I/O37 (io), 73 I/O38 (io), 74 NC, 75 NC, 76 NC, 77 NC, 78 I/O39 (io), 79 I/O40 (io), 80 I/O41 (io), 81 I/O42 (io), 82 I/O43 (io), 83 I/O44 (io), 84 I/O45 (io), 85 I/O46 (io), 86 I/O47 (io), 87 GOE1/IN5 (in), 88 GND (power), 89 IN6 (in), 90 I/O48 (io), 91 I/O49 (io), 92 I/O50 (io), 93 I/O51 (io), 94 I/O52 (io), 95 I/O53 (io), 96 I/O54 (io), 97 I/O55 (io), 98 I/O56 (io), 99 NC, 100 NC

## ispLSI1032E-80LJ
designator U?
In-System Programmable High-Density PLD; Note: Pins 25, 42, 44, 61, 67 & 84 have dual function capability; Pins 67 & 84 are software selectable.
footprint PLCC84_N (Leaded Chip Carrier, 84-Leads, Body 29.3x29.3mm, Pitch 1.27mm, IPC Medium Density)
footprint PLCC84_L (Leaded Chip Carrier, 84-Leads, Body 29.3x29.3mm, Pitch 1.27mm, IPC High Density)
footprint PLCC84_M (Leaded Chip Carrier, 84-Leads, Body 29.3x29.3mm, Pitch 1.27mm, IPC Low Density)
3D model 1032E-PLCC84 (84-Pin Leaded Chip Carrier 1.27 mm Pitch)
pins: 1 GND (power), 2 IN6 (in), 3 I/O48 (io), 4 I/O49 (io), 5 I/O50 (io), 6 I/O51 (io), 7 I/O52 (io), 8 I/O53 (io), 9 I/O54 (io), 10 I/O55 (io), 11 I/O56 (io), 12 I/O57 (io), 13 I/O58 (io), 14 I/O59 (io), 15 I/O60 (io), 16 I/O61 (io), 17 I/O62 (io), 18 I/O63 (io), 19 IN7 (in), 20 Y0 (in), 21 VCC (power), 22 GND (power), 23 ~{isp}~{EN} (in), 24 ~{RESET} (in), 25 SDI/IN0 (in), 26 I/O0 (io), 27 I/O1 (io), 28 I/O2 (io), 29 I/O3 (io), 30 I/O4 (io), 31 I/O5 (io), 32 I/O6 (io), 33 I/O7 (io), 34 I/O8 (io), 35 I/O9 (io), 36 I/O10 (io), 37 I/O11 (io), 38 I/O12 (io), 39 I/O13 (io), 40 I/O14 (io), 41 I/O15 (io), 42 MODE/IN1 (in), 43 GND (power), 44 SDO/IN2 (io), 45 I/O16 (io), 46 I/O17 (io), 47 I/O18 (io), 48 I/O19 (io), 49 I/O20 (io), 50 I/O21 (io), 51 I/O22 (io), 52 I/O23 (io), 53 I/O24 (io), 54 I/O25 (io), 55 I/O26 (io), 56 I/O27 (io), 57 I/O28 (io), 58 I/O29 (io), 59 I/O30 (io), 60 I/O31 (io), 61 SCLK/IN3 (in), 62 Y3 (in), 63 Y2 (in), 64 GND (power), 65 VCC (power), 66 Y1 (in), 67 GOE0/IN4 (in), 68 I/O32 (io), 69 I/O33 (io), 70 I/O34 (io), 71 I/O35 (io), 72 I/O36 (io), 73 I/O37 (io), 74 I/O38 (io), 75 I/O39 (io), 76 I/O40 (io), 77 I/O41 (io), 78 I/O42 (io), 79 I/O43 (io), 80 I/O44 (io), 81 I/O45 (io), 82 I/O46 (io), 83 I/O47 (io), 84 GOE1/IN5 (in)

## ispLSI1032E-80LT
designator U?
In-System Programmable High-Density PLD; Note: Pins 16, 37, 39, 60, 66 & 87 have dual function capability; Pins 66 & 87 are software selectable.
footprint TQFP100_N (Thin QFP, 100-Leads, Body 14x14mm, Pitch 0.5mm, IPC Medium Density)
footprint TQFP100_L (Thin QFP, 100-Leads, Body 14x14mm, Pitch 0.5mm, IPC High Density)
footprint TQFP100_M (Thin QFP, 100-Leads, Body 14x14mm, Pitch 0.5mm, IPC Low Density)
3D model 1032E-TQFP100 (100-Pin Thin Quad Flat Pack (TQFP100))
pins: 1 NC, 2 NC, 3 I/O57 (io), 4 I/O58 (io), 5 I/O59 (io), 6 I/O60 (io), 7 I/O61 (io), 8 I/O62 (io), 9 I/O63 (io), 10 IN7 (in), 11 Y0 (in), 12 VCC (power), 13 GND (power), 14 ~{ispEN} (in), 15 ~{RESET} (in), 16 SDI/IN0 (in), 17 I/O0 (io), 18 I/O1 (io), 19 I/O2 (io), 20 I/O3 (io), 21 I/O4 (io), 22 I/O5 (io), 23 I/O6 (io), 24 NC, 25 NC, 26 NC, 27 NC, 28 I/O7 (io), 29 I/O8 (io), 30 I/O9 (io), 31 I/O10 (io), 32 I/O11 (io), 33 I/O12 (io), 34 I/O13 (io), 35 I/O14 (io), 36 I/O15 (io), 37 MODE/IN1 (in), 38 GND (power), 39 SDO/IN2 (io), 40 I/O16 (io), 41 I/O17 (io), 42 I/O18 (io), 43 I/O19 (io), 44 I/O20 (io), 45 I/O21 (io), 46 I/O22 (io), 47 I/O23 (io), 48 I/O24 (io), 49 NC, 50 NC, 51 NC, 52 NC, 53 I/O25 (io), 54 I/O26 (io), 55 I/O27 (io), 56 I/O28 (io), 57 I/O29 (io), 58 I/O30 (io), 59 I/O31 (io), 60 SCLK/IN3 (in), 61 Y3 (in), 62 Y2 (in), 63 GND (power), 64 VCC (power), 65 Y1 (in), 66 GOE0/IN4 (in), 67 I/O32 (io), 68 I/O33 (io), 69 I/O34 (io), 70 I/O35 (io), 71 I/O36 (io), 72 I/O37 (io), 73 I/O38 (io), 74 NC, 75 NC, 76 NC, 77 NC, 78 I/O39 (io), 79 I/O40 (io), 80 I/O41 (io), 81 I/O42 (io), 82 I/O43 (io), 83 I/O44 (io), 84 I/O45 (io), 85 I/O46 (io), 86 I/O47 (io), 87 GOE1/IN5 (in), 88 GND (power), 89 IN6 (in), 90 I/O48 (io), 91 I/O49 (io), 92 I/O50 (io), 93 I/O51 (io), 94 I/O52 (io), 95 I/O53 (io), 96 I/O54 (io), 97 I/O55 (io), 98 I/O56 (io), 99 NC, 100 NC

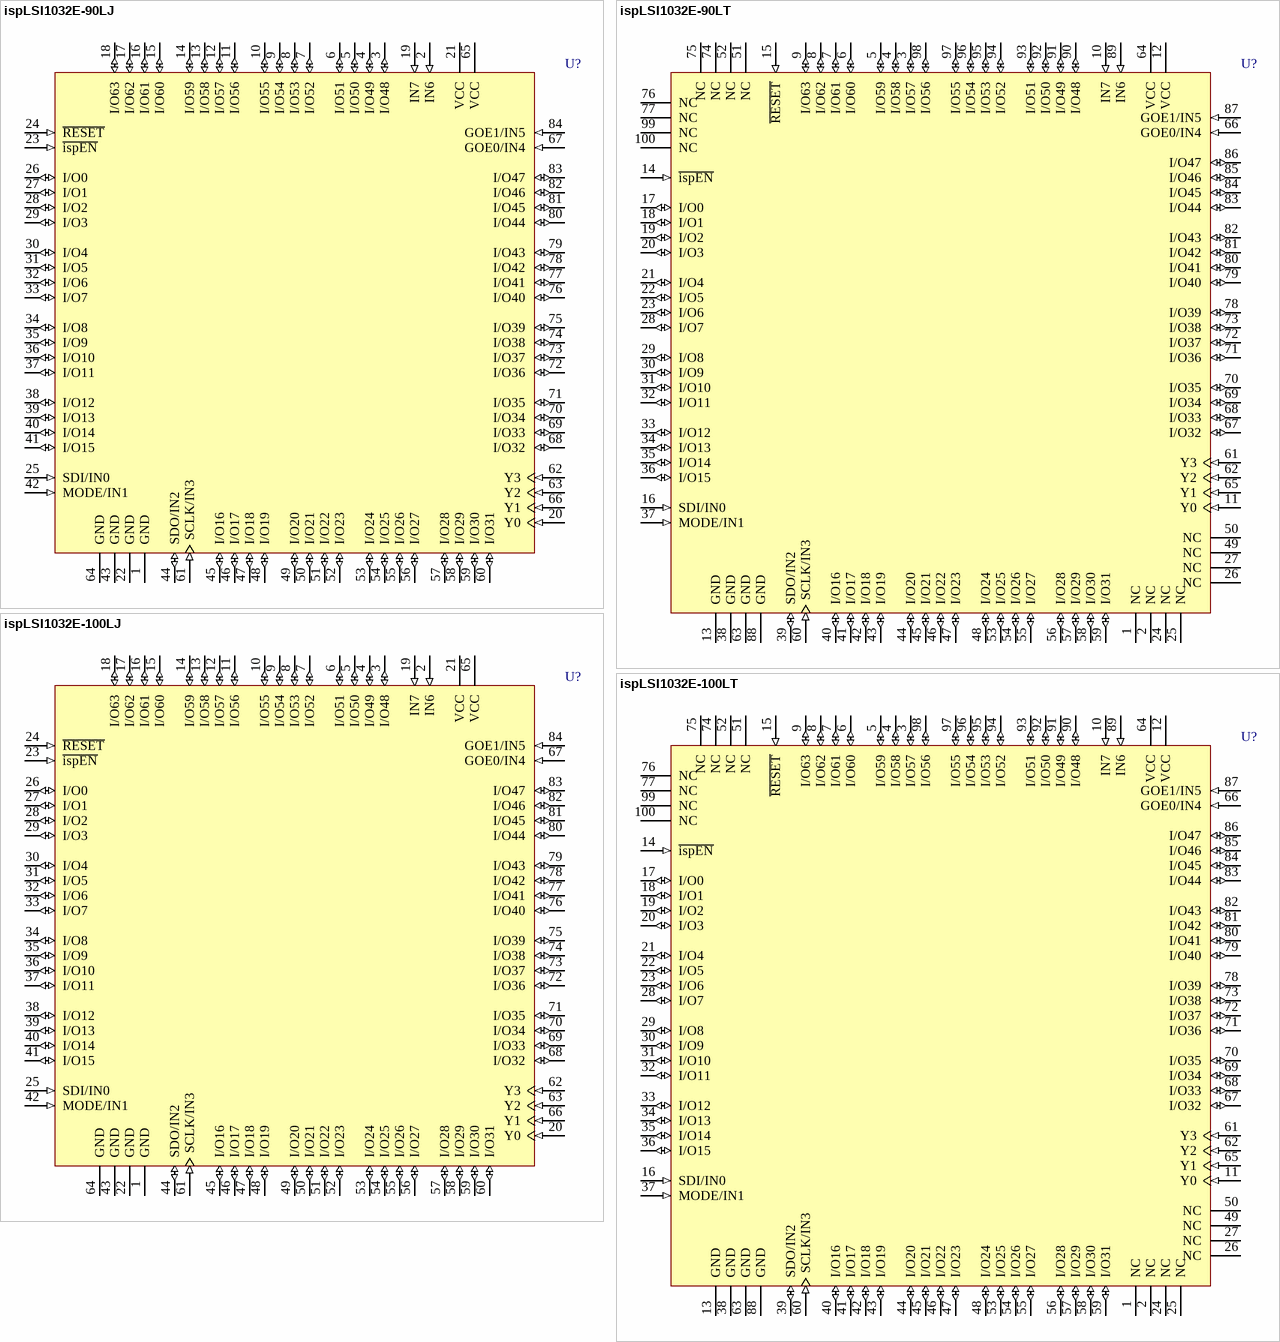
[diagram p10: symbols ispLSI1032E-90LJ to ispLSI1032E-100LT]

## ispLSI1032E-90LJ
designator U?
In-System Programmable High-Density PLD; Note: Pins 25, 42, 44, 61, 67 & 84 have dual function capability; Pins 67 & 84 are software selectable.
footprint PLCC84_N (Leaded Chip Carrier, 84-Leads, Body 29.3x29.3mm, Pitch 1.27mm, IPC Medium Density)
footprint PLCC84_L (Leaded Chip Carrier, 84-Leads, Body 29.3x29.3mm, Pitch 1.27mm, IPC High Density)
footprint PLCC84_M (Leaded Chip Carrier, 84-Leads, Body 29.3x29.3mm, Pitch 1.27mm, IPC Low Density)
3D model 1032E-PLCC84 (84-Pin Leaded Chip Carrier 1.27 mm Pitch)
pins: 1 GND (power), 2 IN6 (in), 3 I/O48 (io), 4 I/O49 (io), 5 I/O50 (io), 6 I/O51 (io), 7 I/O52 (io), 8 I/O53 (io), 9 I/O54 (io), 10 I/O55 (io), 11 I/O56 (io), 12 I/O57 (io), 13 I/O58 (io), 14 I/O59 (io), 15 I/O60 (io), 16 I/O61 (io), 17 I/O62 (io), 18 I/O63 (io), 19 IN7 (in), 20 Y0 (in), 21 VCC (power), 22 GND (power), 23 ~{isp}~{EN} (in), 24 ~{RESET} (in), 25 SDI/IN0 (in), 26 I/O0 (io), 27 I/O1 (io), 28 I/O2 (io), 29 I/O3 (io), 30 I/O4 (io), 31 I/O5 (io), 32 I/O6 (io), 33 I/O7 (io), 34 I/O8 (io), 35 I/O9 (io), 36 I/O10 (io), 37 I/O11 (io), 38 I/O12 (io), 39 I/O13 (io), 40 I/O14 (io), 41 I/O15 (io), 42 MODE/IN1 (in), 43 GND (power), 44 SDO/IN2 (io), 45 I/O16 (io), 46 I/O17 (io), 47 I/O18 (io), 48 I/O19 (io), 49 I/O20 (io), 50 I/O21 (io), 51 I/O22 (io), 52 I/O23 (io), 53 I/O24 (io), 54 I/O25 (io), 55 I/O26 (io), 56 I/O27 (io), 57 I/O28 (io), 58 I/O29 (io), 59 I/O30 (io), 60 I/O31 (io), 61 SCLK/IN3 (in), 62 Y3 (in), 63 Y2 (in), 64 GND (power), 65 VCC (power), 66 Y1 (in), 67 GOE0/IN4 (in), 68 I/O32 (io), 69 I/O33 (io), 70 I/O34 (io), 71 I/O35 (io), 72 I/O36 (io), 73 I/O37 (io), 74 I/O38 (io), 75 I/O39 (io), 76 I/O40 (io), 77 I/O41 (io), 78 I/O42 (io), 79 I/O43 (io), 80 I/O44 (io), 81 I/O45 (io), 82 I/O46 (io), 83 I/O47 (io), 84 GOE1/IN5 (in)

## ispLSI1032E-90LT
designator U?
In-System Programmable High-Density PLD; Note: Pins 16, 37, 39, 60, 66 & 87 have dual function capability; Pins 66 & 87 are software selectable.
footprint TQFP100_N (Thin QFP, 100-Leads, Body 14x14mm, Pitch 0.5mm, IPC Medium Density)
footprint TQFP100_L (Thin QFP, 100-Leads, Body 14x14mm, Pitch 0.5mm, IPC High Density)
footprint TQFP100_M (Thin QFP, 100-Leads, Body 14x14mm, Pitch 0.5mm, IPC Low Density)
3D model 1032E-TQFP100 (100-Pin Thin Quad Flat Pack (TQFP100))
pins: 1 NC, 2 NC, 3 I/O57 (io), 4 I/O58 (io), 5 I/O59 (io), 6 I/O60 (io), 7 I/O61 (io), 8 I/O62 (io), 9 I/O63 (io), 10 IN7 (in), 11 Y0 (in), 12 VCC (power), 13 GND (power), 14 ~{ispEN} (in), 15 ~{RESET} (in), 16 SDI/IN0 (in), 17 I/O0 (io), 18 I/O1 (io), 19 I/O2 (io), 20 I/O3 (io), 21 I/O4 (io), 22 I/O5 (io), 23 I/O6 (io), 24 NC, 25 NC, 26 NC, 27 NC, 28 I/O7 (io), 29 I/O8 (io), 30 I/O9 (io), 31 I/O10 (io), 32 I/O11 (io), 33 I/O12 (io), 34 I/O13 (io), 35 I/O14 (io), 36 I/O15 (io), 37 MODE/IN1 (in), 38 GND (power), 39 SDO/IN2 (io), 40 I/O16 (io), 41 I/O17 (io), 42 I/O18 (io), 43 I/O19 (io), 44 I/O20 (io), 45 I/O21 (io), 46 I/O22 (io), 47 I/O23 (io), 48 I/O24 (io), 49 NC, 50 NC, 51 NC, 52 NC, 53 I/O25 (io), 54 I/O26 (io), 55 I/O27 (io), 56 I/O28 (io), 57 I/O29 (io), 58 I/O30 (io), 59 I/O31 (io), 60 SCLK/IN3 (in), 61 Y3 (in), 62 Y2 (in), 63 GND (power), 64 VCC (power), 65 Y1 (in), 66 GOE0/IN4 (in), 67 I/O32 (io), 68 I/O33 (io), 69 I/O34 (io), 70 I/O35 (io), 71 I/O36 (io), 72 I/O37 (io), 73 I/O38 (io), 74 NC, 75 NC, 76 NC, 77 NC, 78 I/O39 (io), 79 I/O40 (io), 80 I/O41 (io), 81 I/O42 (io), 82 I/O43 (io), 83 I/O44 (io), 84 I/O45 (io), 85 I/O46 (io), 86 I/O47 (io), 87 GOE1/IN5 (in), 88 GND (power), 89 IN6 (in), 90 I/O48 (io), 91 I/O49 (io), 92 I/O50 (io), 93 I/O51 (io), 94 I/O52 (io), 95 I/O53 (io), 96 I/O54 (io), 97 I/O55 (io), 98 I/O56 (io), 99 NC, 100 NC

## ispLSI1032E-100LJ
designator U?
In-System Programmable High-Density PLD; Note: Pins 25, 42, 44, 61, 67 & 84 have dual function capability; Pins 67 & 84 are software selectable.
footprint PLCC84_N (Leaded Chip Carrier, 84-Leads, Body 29.3x29.3mm, Pitch 1.27mm, IPC Medium Density)
footprint PLCC84_L (Leaded Chip Carrier, 84-Leads, Body 29.3x29.3mm, Pitch 1.27mm, IPC High Density)
footprint PLCC84_M (Leaded Chip Carrier, 84-Leads, Body 29.3x29.3mm, Pitch 1.27mm, IPC Low Density)
3D model 1032E-PLCC84 (84-Pin Leaded Chip Carrier 1.27 mm Pitch)
pins: 1 GND (power), 2 IN6 (in), 3 I/O48 (io), 4 I/O49 (io), 5 I/O50 (io), 6 I/O51 (io), 7 I/O52 (io), 8 I/O53 (io), 9 I/O54 (io), 10 I/O55 (io), 11 I/O56 (io), 12 I/O57 (io), 13 I/O58 (io), 14 I/O59 (io), 15 I/O60 (io), 16 I/O61 (io), 17 I/O62 (io), 18 I/O63 (io), 19 IN7 (in), 20 Y0 (in), 21 VCC (power), 22 GND (power), 23 ~{isp}~{EN} (in), 24 ~{RESET} (in), 25 SDI/IN0 (in), 26 I/O0 (io), 27 I/O1 (io), 28 I/O2 (io), 29 I/O3 (io), 30 I/O4 (io), 31 I/O5 (io), 32 I/O6 (io), 33 I/O7 (io), 34 I/O8 (io), 35 I/O9 (io), 36 I/O10 (io), 37 I/O11 (io), 38 I/O12 (io), 39 I/O13 (io), 40 I/O14 (io), 41 I/O15 (io), 42 MODE/IN1 (in), 43 GND (power), 44 SDO/IN2 (io), 45 I/O16 (io), 46 I/O17 (io), 47 I/O18 (io), 48 I/O19 (io), 49 I/O20 (io), 50 I/O21 (io), 51 I/O22 (io), 52 I/O23 (io), 53 I/O24 (io), 54 I/O25 (io), 55 I/O26 (io), 56 I/O27 (io), 57 I/O28 (io), 58 I/O29 (io), 59 I/O30 (io), 60 I/O31 (io), 61 SCLK/IN3 (in), 62 Y3 (in), 63 Y2 (in), 64 GND (power), 65 VCC (power), 66 Y1 (in), 67 GOE0/IN4 (in), 68 I/O32 (io), 69 I/O33 (io), 70 I/O34 (io), 71 I/O35 (io), 72 I/O36 (io), 73 I/O37 (io), 74 I/O38 (io), 75 I/O39 (io), 76 I/O40 (io), 77 I/O41 (io), 78 I/O42 (io), 79 I/O43 (io), 80 I/O44 (io), 81 I/O45 (io), 82 I/O46 (io), 83 I/O47 (io), 84 GOE1/IN5 (in)

## ispLSI1032E-100LT
designator U?
In-System Programmable High-Density PLD; Note: Pins 16, 37, 39, 60, 66 & 87 have dual function capability; Pins 66 & 87 are software selectable.
footprint TQFP100_N (Thin QFP, 100-Leads, Body 14x14mm, Pitch 0.5mm, IPC Medium Density)
footprint TQFP100_L (Thin QFP, 100-Leads, Body 14x14mm, Pitch 0.5mm, IPC High Density)
footprint TQFP100_M (Thin QFP, 100-Leads, Body 14x14mm, Pitch 0.5mm, IPC Low Density)
3D model 1032E-TQFP100 (100-Pin Thin Quad Flat Pack (TQFP100))
pins: 1 NC, 2 NC, 3 I/O57 (io), 4 I/O58 (io), 5 I/O59 (io), 6 I/O60 (io), 7 I/O61 (io), 8 I/O62 (io), 9 I/O63 (io), 10 IN7 (in), 11 Y0 (in), 12 VCC (power), 13 GND (power), 14 ~{ispEN} (in), 15 ~{RESET} (in), 16 SDI/IN0 (in), 17 I/O0 (io), 18 I/O1 (io), 19 I/O2 (io), 20 I/O3 (io), 21 I/O4 (io), 22 I/O5 (io), 23 I/O6 (io), 24 NC, 25 NC, 26 NC, 27 NC, 28 I/O7 (io), 29 I/O8 (io), 30 I/O9 (io), 31 I/O10 (io), 32 I/O11 (io), 33 I/O12 (io), 34 I/O13 (io), 35 I/O14 (io), 36 I/O15 (io), 37 MODE/IN1 (in), 38 GND (power), 39 SDO/IN2 (io), 40 I/O16 (io), 41 I/O17 (io), 42 I/O18 (io), 43 I/O19 (io), 44 I/O20 (io), 45 I/O21 (io), 46 I/O22 (io), 47 I/O23 (io), 48 I/O24 (io), 49 NC, 50 NC, 51 NC, 52 NC, 53 I/O25 (io), 54 I/O26 (io), 55 I/O27 (io), 56 I/O28 (io), 57 I/O29 (io), 58 I/O30 (io), 59 I/O31 (io), 60 SCLK/IN3 (in), 61 Y3 (in), 62 Y2 (in), 63 GND (power), 64 VCC (power), 65 Y1 (in), 66 GOE0/IN4 (in), 67 I/O32 (io), 68 I/O33 (io), 69 I/O34 (io), 70 I/O35 (io), 71 I/O36 (io), 72 I/O37 (io), 73 I/O38 (io), 74 NC, 75 NC, 76 NC, 77 NC, 78 I/O39 (io), 79 I/O40 (io), 80 I/O41 (io), 81 I/O42 (io), 82 I/O43 (io), 83 I/O44 (io), 84 I/O45 (io), 85 I/O46 (io), 86 I/O47 (io), 87 GOE1/IN5 (in), 88 GND (power), 89 IN6 (in), 90 I/O48 (io), 91 I/O49 (io), 92 I/O50 (io), 93 I/O51 (io), 94 I/O52 (io), 95 I/O53 (io), 96 I/O54 (io), 97 I/O55 (io), 98 I/O56 (io), 99 NC, 100 NC

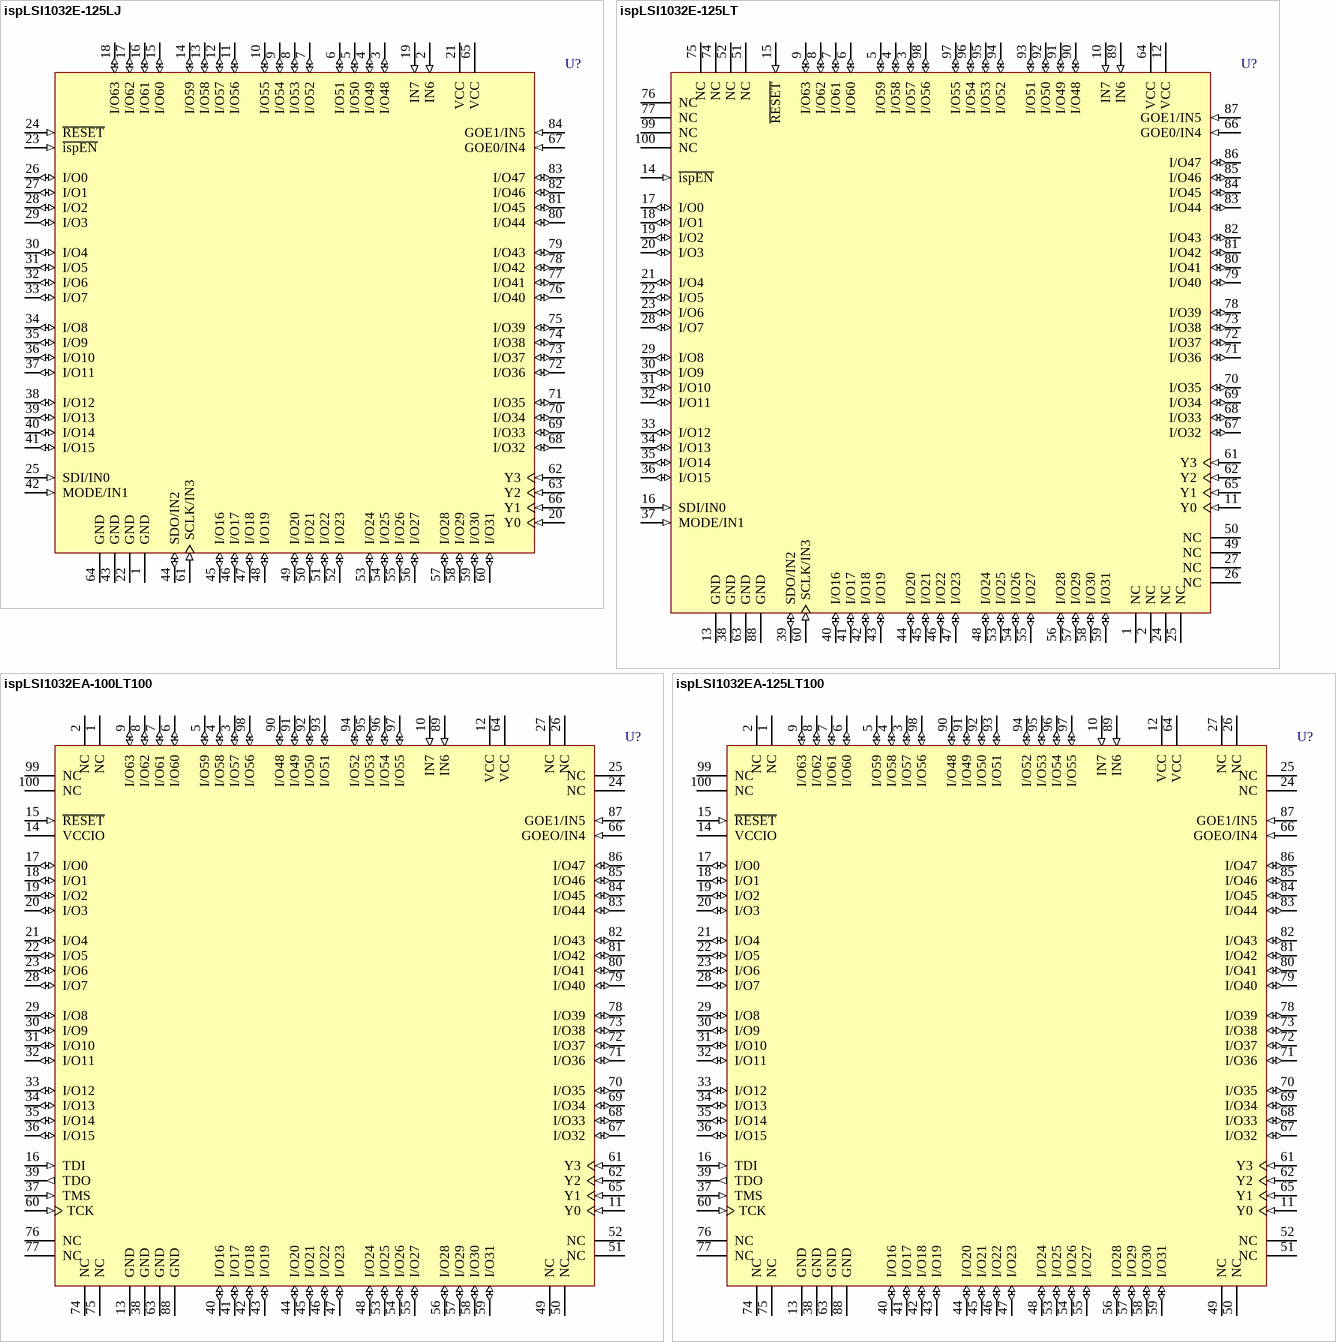
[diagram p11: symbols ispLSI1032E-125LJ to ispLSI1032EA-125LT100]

## ispLSI1032E-125LJ
designator U?
In-System Programmable High-Density PLD; Note: Pins 25, 42, 44, 61, 67 & 84 have dual function capability; Pins 67 & 84 are software selectable.
footprint PLCC84_N (Leaded Chip Carrier, 84-Leads, Body 29.3x29.3mm, Pitch 1.27mm, IPC Medium Density)
footprint PLCC84_L (Leaded Chip Carrier, 84-Leads, Body 29.3x29.3mm, Pitch 1.27mm, IPC High Density)
footprint PLCC84_M (Leaded Chip Carrier, 84-Leads, Body 29.3x29.3mm, Pitch 1.27mm, IPC Low Density)
3D model 1032E-PLCC84 (84-Pin Leaded Chip Carrier 1.27 mm Pitch)
pins: 1 GND (power), 2 IN6 (in), 3 I/O48 (io), 4 I/O49 (io), 5 I/O50 (io), 6 I/O51 (io), 7 I/O52 (io), 8 I/O53 (io), 9 I/O54 (io), 10 I/O55 (io), 11 I/O56 (io), 12 I/O57 (io), 13 I/O58 (io), 14 I/O59 (io), 15 I/O60 (io), 16 I/O61 (io), 17 I/O62 (io), 18 I/O63 (io), 19 IN7 (in), 20 Y0 (in), 21 VCC (power), 22 GND (power), 23 ~{isp}~{EN} (in), 24 ~{RESET} (in), 25 SDI/IN0 (in), 26 I/O0 (io), 27 I/O1 (io), 28 I/O2 (io), 29 I/O3 (io), 30 I/O4 (io), 31 I/O5 (io), 32 I/O6 (io), 33 I/O7 (io), 34 I/O8 (io), 35 I/O9 (io), 36 I/O10 (io), 37 I/O11 (io), 38 I/O12 (io), 39 I/O13 (io), 40 I/O14 (io), 41 I/O15 (io), 42 MODE/IN1 (in), 43 GND (power), 44 SDO/IN2 (io), 45 I/O16 (io), 46 I/O17 (io), 47 I/O18 (io), 48 I/O19 (io), 49 I/O20 (io), 50 I/O21 (io), 51 I/O22 (io), 52 I/O23 (io), 53 I/O24 (io), 54 I/O25 (io), 55 I/O26 (io), 56 I/O27 (io), 57 I/O28 (io), 58 I/O29 (io), 59 I/O30 (io), 60 I/O31 (io), 61 SCLK/IN3 (in), 62 Y3 (in), 63 Y2 (in), 64 GND (power), 65 VCC (power), 66 Y1 (in), 67 GOE0/IN4 (in), 68 I/O32 (io), 69 I/O33 (io), 70 I/O34 (io), 71 I/O35 (io), 72 I/O36 (io), 73 I/O37 (io), 74 I/O38 (io), 75 I/O39 (io), 76 I/O40 (io), 77 I/O41 (io), 78 I/O42 (io), 79 I/O43 (io), 80 I/O44 (io), 81 I/O45 (io), 82 I/O46 (io), 83 I/O47 (io), 84 GOE1/IN5 (in)

## ispLSI1032E-125LT
designator U?
In-System Programmable High-Density PLD; Note: Pins 16, 37, 39, 60, 66 & 87 have dual function capability; Pins 66 & 87 are software selectable.
footprint TQFP100_N (Thin QFP, 100-Leads, Body 14x14mm, Pitch 0.5mm, IPC Medium Density)
footprint TQFP100_L (Thin QFP, 100-Leads, Body 14x14mm, Pitch 0.5mm, IPC High Density)
footprint TQFP100_M (Thin QFP, 100-Leads, Body 14x14mm, Pitch 0.5mm, IPC Low Density)
3D model 1032E-TQFP100 (100-Pin Thin Quad Flat Pack (TQFP100))
pins: 1 NC, 2 NC, 3 I/O57 (io), 4 I/O58 (io), 5 I/O59 (io), 6 I/O60 (io), 7 I/O61 (io), 8 I/O62 (io), 9 I/O63 (io), 10 IN7 (in), 11 Y0 (in), 12 VCC (power), 13 GND (power), 14 ~{ispEN} (in), 15 ~{RESET} (in), 16 SDI/IN0 (in), 17 I/O0 (io), 18 I/O1 (io), 19 I/O2 (io), 20 I/O3 (io), 21 I/O4 (io), 22 I/O5 (io), 23 I/O6 (io), 24 NC, 25 NC, 26 NC, 27 NC, 28 I/O7 (io), 29 I/O8 (io), 30 I/O9 (io), 31 I/O10 (io), 32 I/O11 (io), 33 I/O12 (io), 34 I/O13 (io), 35 I/O14 (io), 36 I/O15 (io), 37 MODE/IN1 (in), 38 GND (power), 39 SDO/IN2 (io), 40 I/O16 (io), 41 I/O17 (io), 42 I/O18 (io), 43 I/O19 (io), 44 I/O20 (io), 45 I/O21 (io), 46 I/O22 (io), 47 I/O23 (io), 48 I/O24 (io), 49 NC, 50 NC, 51 NC, 52 NC, 53 I/O25 (io), 54 I/O26 (io), 55 I/O27 (io), 56 I/O28 (io), 57 I/O29 (io), 58 I/O30 (io), 59 I/O31 (io), 60 SCLK/IN3 (in), 61 Y3 (in), 62 Y2 (in), 63 GND (power), 64 VCC (power), 65 Y1 (in), 66 GOE0/IN4 (in), 67 I/O32 (io), 68 I/O33 (io), 69 I/O34 (io), 70 I/O35 (io), 71 I/O36 (io), 72 I/O37 (io), 73 I/O38 (io), 74 NC, 75 NC, 76 NC, 77 NC, 78 I/O39 (io), 79 I/O40 (io), 80 I/O41 (io), 81 I/O42 (io), 82 I/O43 (io), 83 I/O44 (io), 84 I/O45 (io), 85 I/O46 (io), 86 I/O47 (io), 87 GOE1/IN5 (in), 88 GND (power), 89 IN6 (in), 90 I/O48 (io), 91 I/O49 (io), 92 I/O50 (io), 93 I/O51 (io), 94 I/O52 (io), 95 I/O53 (io), 96 I/O54 (io), 97 I/O55 (io), 98 I/O56 (io), 99 NC, 100 NC

## ispLSI1032EA-100LT100
designator U?
In-System Programmable High-Density PLD; Note: Pins 66 and 87 have dual function capability which is software selectable.
footprint TQFP100_N (Thin QFP, 100-Leads, Body 14x14mm, Pitch 0.5mm, IPC Medium Density)
footprint TQFP100_L (Thin QFP, 100-Leads, Body 14x14mm, Pitch 0.5mm, IPC High Density)
footprint TQFP100_M (Thin QFP, 100-Leads, Body 14x14mm, Pitch 0.5mm, IPC Low Density)
3D model 1032EA-TQFP100 (100-Pin Thin Quad Flat Pack (TQFP100))
pins: 1 NC, 2 NC, 3 I/O57 (io), 4 I/O58 (io), 5 I/O59 (io), 6 I/O60 (io), 7 I/O61 (io), 8 I/O62 (io), 9 I/O63 (io), 10 IN7 (in), 11 Y0 (in), 12 VCC (power), 13 GND (power), 14 VCCIO (power), 15 ~{RESET} (in), 16 TDI (in), 17 I/O0 (io), 18 I/O1 (io), 19 I/O2 (io), 20 I/O3 (io), 21 I/O4 (io), 22 I/O5 (io), 23 I/O6 (io), 24 NC, 25 NC, 26 NC, 27 NC, 28 I/O7 (io), 29 I/O8 (io), 30 I/O9 (io), 31 I/O10 (io), 32 I/O11 (io), 33 I/O12 (io), 34 I/O13 (io), 35 I/O14 (io), 36 I/O15 (io), 37 TMS (in), 38 GND (power), 39 TDO (out), 40 I/O16 (io), 41 I/O17 (io), 42 I/O18 (io), 43 I/O19 (io), 44 I/O20 (io), 45 I/O21 (io), 46 I/O22 (io), 47 I/O23 (io), 48 I/O24 (io), 49 NC, 50 NC, 51 NC, 52 NC, 53 I/O25 (io), 54 I/O26 (io), 55 I/O27 (io), 56 I/O28 (io), 57 I/O29 (io), 58 I/O30 (io), 59 I/O31 (io), 60 TCK (in), 61 Y3 (in), 62 Y2 (in), 63 GND (power), 64 VCC (power), 65 Y1 (in), 66 GOEO/IN4 (in), 67 I/O32 (io), 68 I/O33 (io), 69 I/O34 (io), 70 I/O35 (io), 71 I/O36 (io), 72 I/O37 (io), 73 I/O38 (io), 74 NC, 75 NC, 76 NC, 77 NC, 78 I/O39 (io), 79 I/O40 (io), 80 I/O41 (io), 81 I/O42 (io), 82 I/O43 (io), 83 I/O44 (io), 84 I/O45 (io), 85 I/O46 (io), 86 I/O47 (io), 87 GOE1/IN5 (in), 88 GND (power), 89 IN6 (in), 90 I/O48 (io), 91 I/O49 (io), 92 I/O50 (io), 93 I/O51 (io), 94 I/O52 (io), 95 I/O53 (io), 96 I/O54 (io), 97 I/O55 (io), 98 I/O56 (io), 99 NC, 100 NC

## ispLSI1032EA-125LT100
designator U?
In-System Programmable High-Density PLD; Note: Pins 66 and 87 have dual function capability which is software selectable.
footprint TQFP100_N (Thin QFP, 100-Leads, Body 14x14mm, Pitch 0.5mm, IPC Medium Density)
footprint TQFP100_L (Thin QFP, 100-Leads, Body 14x14mm, Pitch 0.5mm, IPC High Density)
footprint TQFP100_M (Thin QFP, 100-Leads, Body 14x14mm, Pitch 0.5mm, IPC Low Density)
3D model 1032EA-TQFP100 (100-Pin Thin Quad Flat Pack (TQFP100))
pins: 1 NC, 2 NC, 3 I/O57 (io), 4 I/O58 (io), 5 I/O59 (io), 6 I/O60 (io), 7 I/O61 (io), 8 I/O62 (io), 9 I/O63 (io), 10 IN7 (in), 11 Y0 (in), 12 VCC (power), 13 GND (power), 14 VCCIO (power), 15 ~{RESET} (in), 16 TDI (in), 17 I/O0 (io), 18 I/O1 (io), 19 I/O2 (io), 20 I/O3 (io), 21 I/O4 (io), 22 I/O5 (io), 23 I/O6 (io), 24 NC, 25 NC, 26 NC, 27 NC, 28 I/O7 (io), 29 I/O8 (io), 30 I/O9 (io), 31 I/O10 (io), 32 I/O11 (io), 33 I/O12 (io), 34 I/O13 (io), 35 I/O14 (io), 36 I/O15 (io), 37 TMS (in), 38 GND (power), 39 TDO (out), 40 I/O16 (io), 41 I/O17 (io), 42 I/O18 (io), 43 I/O19 (io), 44 I/O20 (io), 45 I/O21 (io), 46 I/O22 (io), 47 I/O23 (io), 48 I/O24 (io), 49 NC, 50 NC, 51 NC, 52 NC, 53 I/O25 (io), 54 I/O26 (io), 55 I/O27 (io), 56 I/O28 (io), 57 I/O29 (io), 58 I/O30 (io), 59 I/O31 (io), 60 TCK (in), 61 Y3 (in), 62 Y2 (in), 63 GND (power), 64 VCC (power), 65 Y1 (in), 66 GOEO/IN4 (in), 67 I/O32 (io), 68 I/O33 (io), 69 I/O34 (io), 70 I/O35 (io), 71 I/O36 (io), 72 I/O37 (io), 73 I/O38 (io), 74 NC, 75 NC, 76 NC, 77 NC, 78 I/O39 (io), 79 I/O40 (io), 80 I/O41 (io), 81 I/O42 (io), 82 I/O43 (io), 83 I/O44 (io), 84 I/O45 (io), 85 I/O46 (io), 86 I/O47 (io), 87 GOE1/IN5 (in), 88 GND (power), 89 IN6 (in), 90 I/O48 (io), 91 I/O49 (io), 92 I/O50 (io), 93 I/O51 (io), 94 I/O52 (io), 95 I/O53 (io), 96 I/O54 (io), 97 I/O55 (io), 98 I/O56 (io), 99 NC, 100 NC

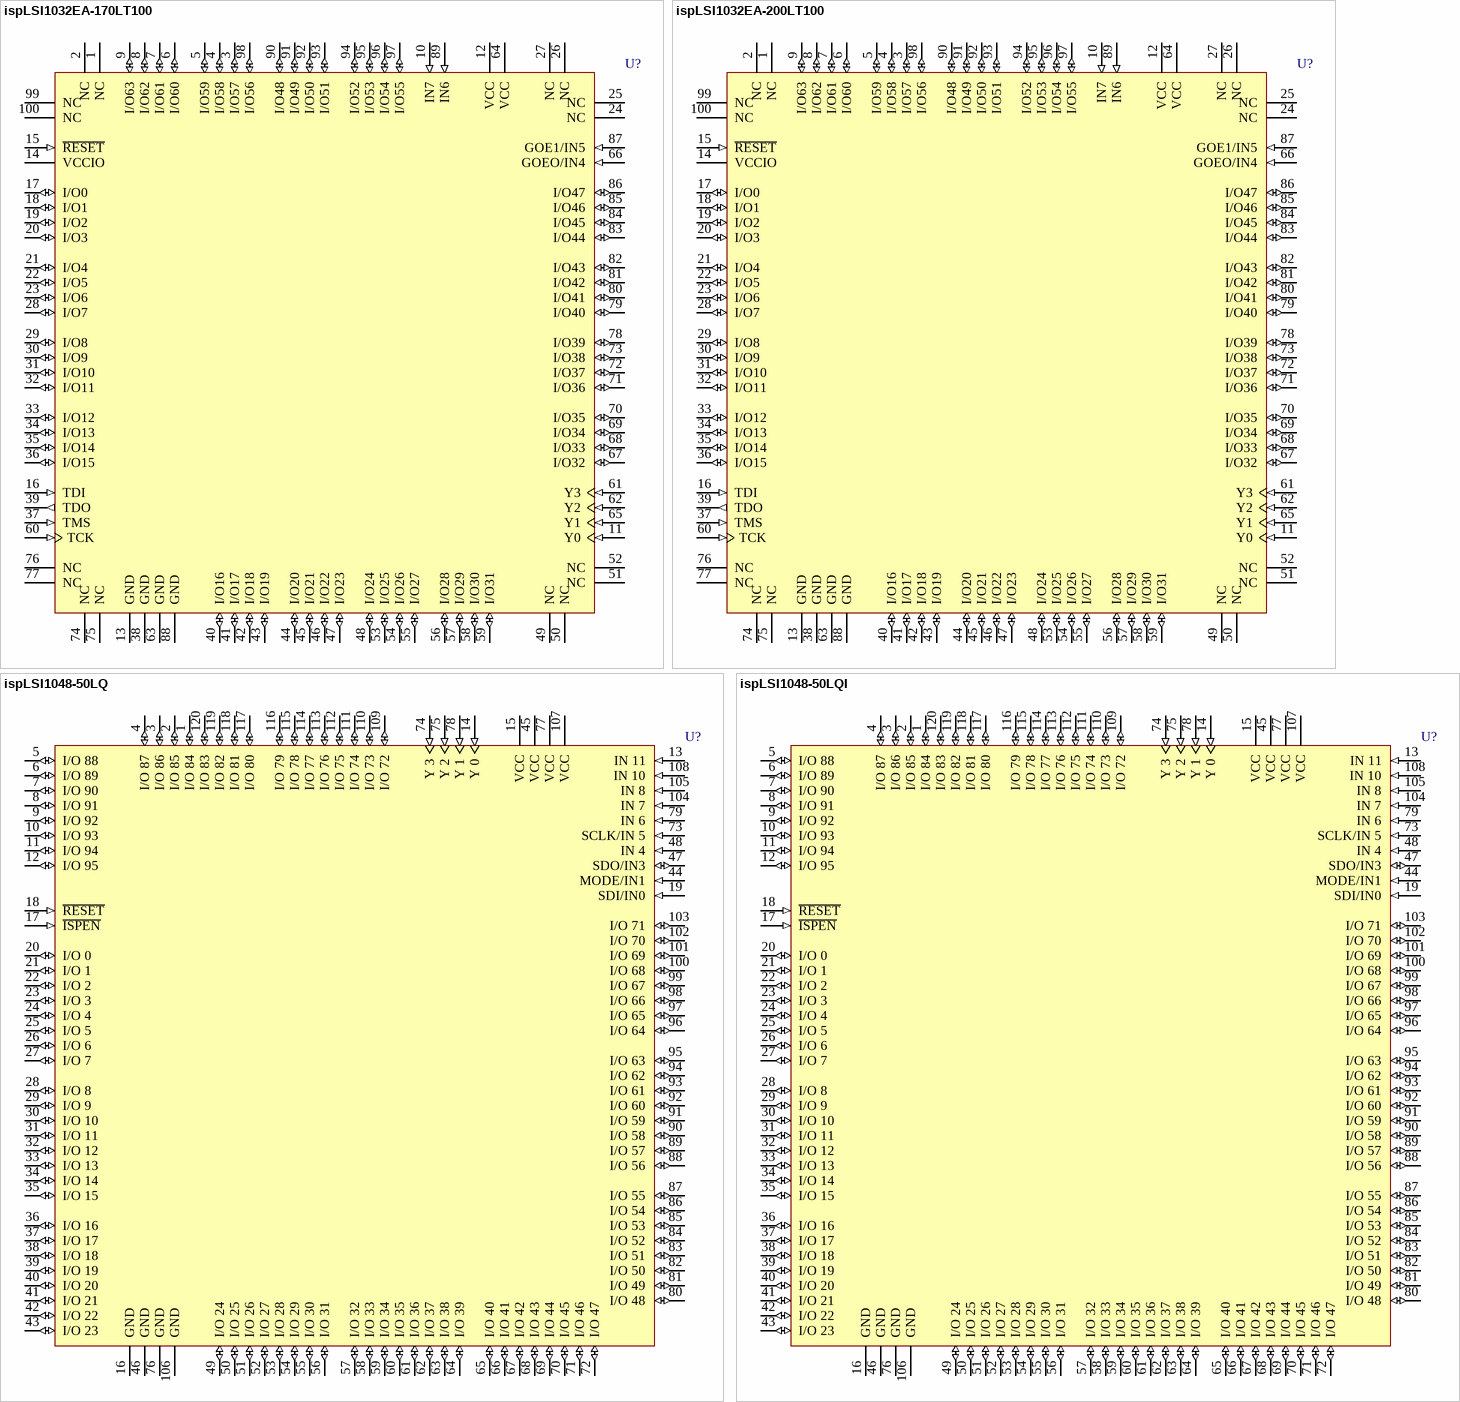
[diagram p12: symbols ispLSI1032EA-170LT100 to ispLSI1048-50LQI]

## ispLSI1032EA-170LT100
designator U?
In-System Programmable High-Density PLD; Note: Pins 66 and 87 have dual function capability which is software selectable.
footprint TQFP100_N (Thin QFP, 100-Leads, Body 14x14mm, Pitch 0.5mm, IPC Medium Density)
footprint TQFP100_L (Thin QFP, 100-Leads, Body 14x14mm, Pitch 0.5mm, IPC High Density)
footprint TQFP100_M (Thin QFP, 100-Leads, Body 14x14mm, Pitch 0.5mm, IPC Low Density)
3D model 1032EA-TQFP100 (100-Pin Thin Quad Flat Pack (TQFP100))
pins: 1 NC, 2 NC, 3 I/O57 (io), 4 I/O58 (io), 5 I/O59 (io), 6 I/O60 (io), 7 I/O61 (io), 8 I/O62 (io), 9 I/O63 (io), 10 IN7 (in), 11 Y0 (in), 12 VCC (power), 13 GND (power), 14 VCCIO (power), 15 ~{RESET} (in), 16 TDI (in), 17 I/O0 (io), 18 I/O1 (io), 19 I/O2 (io), 20 I/O3 (io), 21 I/O4 (io), 22 I/O5 (io), 23 I/O6 (io), 24 NC, 25 NC, 26 NC, 27 NC, 28 I/O7 (io), 29 I/O8 (io), 30 I/O9 (io), 31 I/O10 (io), 32 I/O11 (io), 33 I/O12 (io), 34 I/O13 (io), 35 I/O14 (io), 36 I/O15 (io), 37 TMS (in), 38 GND (power), 39 TDO (out), 40 I/O16 (io), 41 I/O17 (io), 42 I/O18 (io), 43 I/O19 (io), 44 I/O20 (io), 45 I/O21 (io), 46 I/O22 (io), 47 I/O23 (io), 48 I/O24 (io), 49 NC, 50 NC, 51 NC, 52 NC, 53 I/O25 (io), 54 I/O26 (io), 55 I/O27 (io), 56 I/O28 (io), 57 I/O29 (io), 58 I/O30 (io), 59 I/O31 (io), 60 TCK (in), 61 Y3 (in), 62 Y2 (in), 63 GND (power), 64 VCC (power), 65 Y1 (in), 66 GOEO/IN4 (in), 67 I/O32 (io), 68 I/O33 (io), 69 I/O34 (io), 70 I/O35 (io), 71 I/O36 (io), 72 I/O37 (io), 73 I/O38 (io), 74 NC, 75 NC, 76 NC, 77 NC, 78 I/O39 (io), 79 I/O40 (io), 80 I/O41 (io), 81 I/O42 (io), 82 I/O43 (io), 83 I/O44 (io), 84 I/O45 (io), 85 I/O46 (io), 86 I/O47 (io), 87 GOE1/IN5 (in), 88 GND (power), 89 IN6 (in), 90 I/O48 (io), 91 I/O49 (io), 92 I/O50 (io), 93 I/O51 (io), 94 I/O52 (io), 95 I/O53 (io), 96 I/O54 (io), 97 I/O55 (io), 98 I/O56 (io), 99 NC, 100 NC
